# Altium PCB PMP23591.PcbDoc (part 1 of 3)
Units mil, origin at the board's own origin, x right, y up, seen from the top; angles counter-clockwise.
Board outline 3937.01 x 3937.01 mil, 6 copper layers (Top Layer, GND, Power Layer, Signal Layer, GND (Mid4), Bottom Layer), stack 66.824 mil thick; 197 components, 79 nets, 496 pads, 588 vias.
Unrouted connection lines stored in the file: 309.
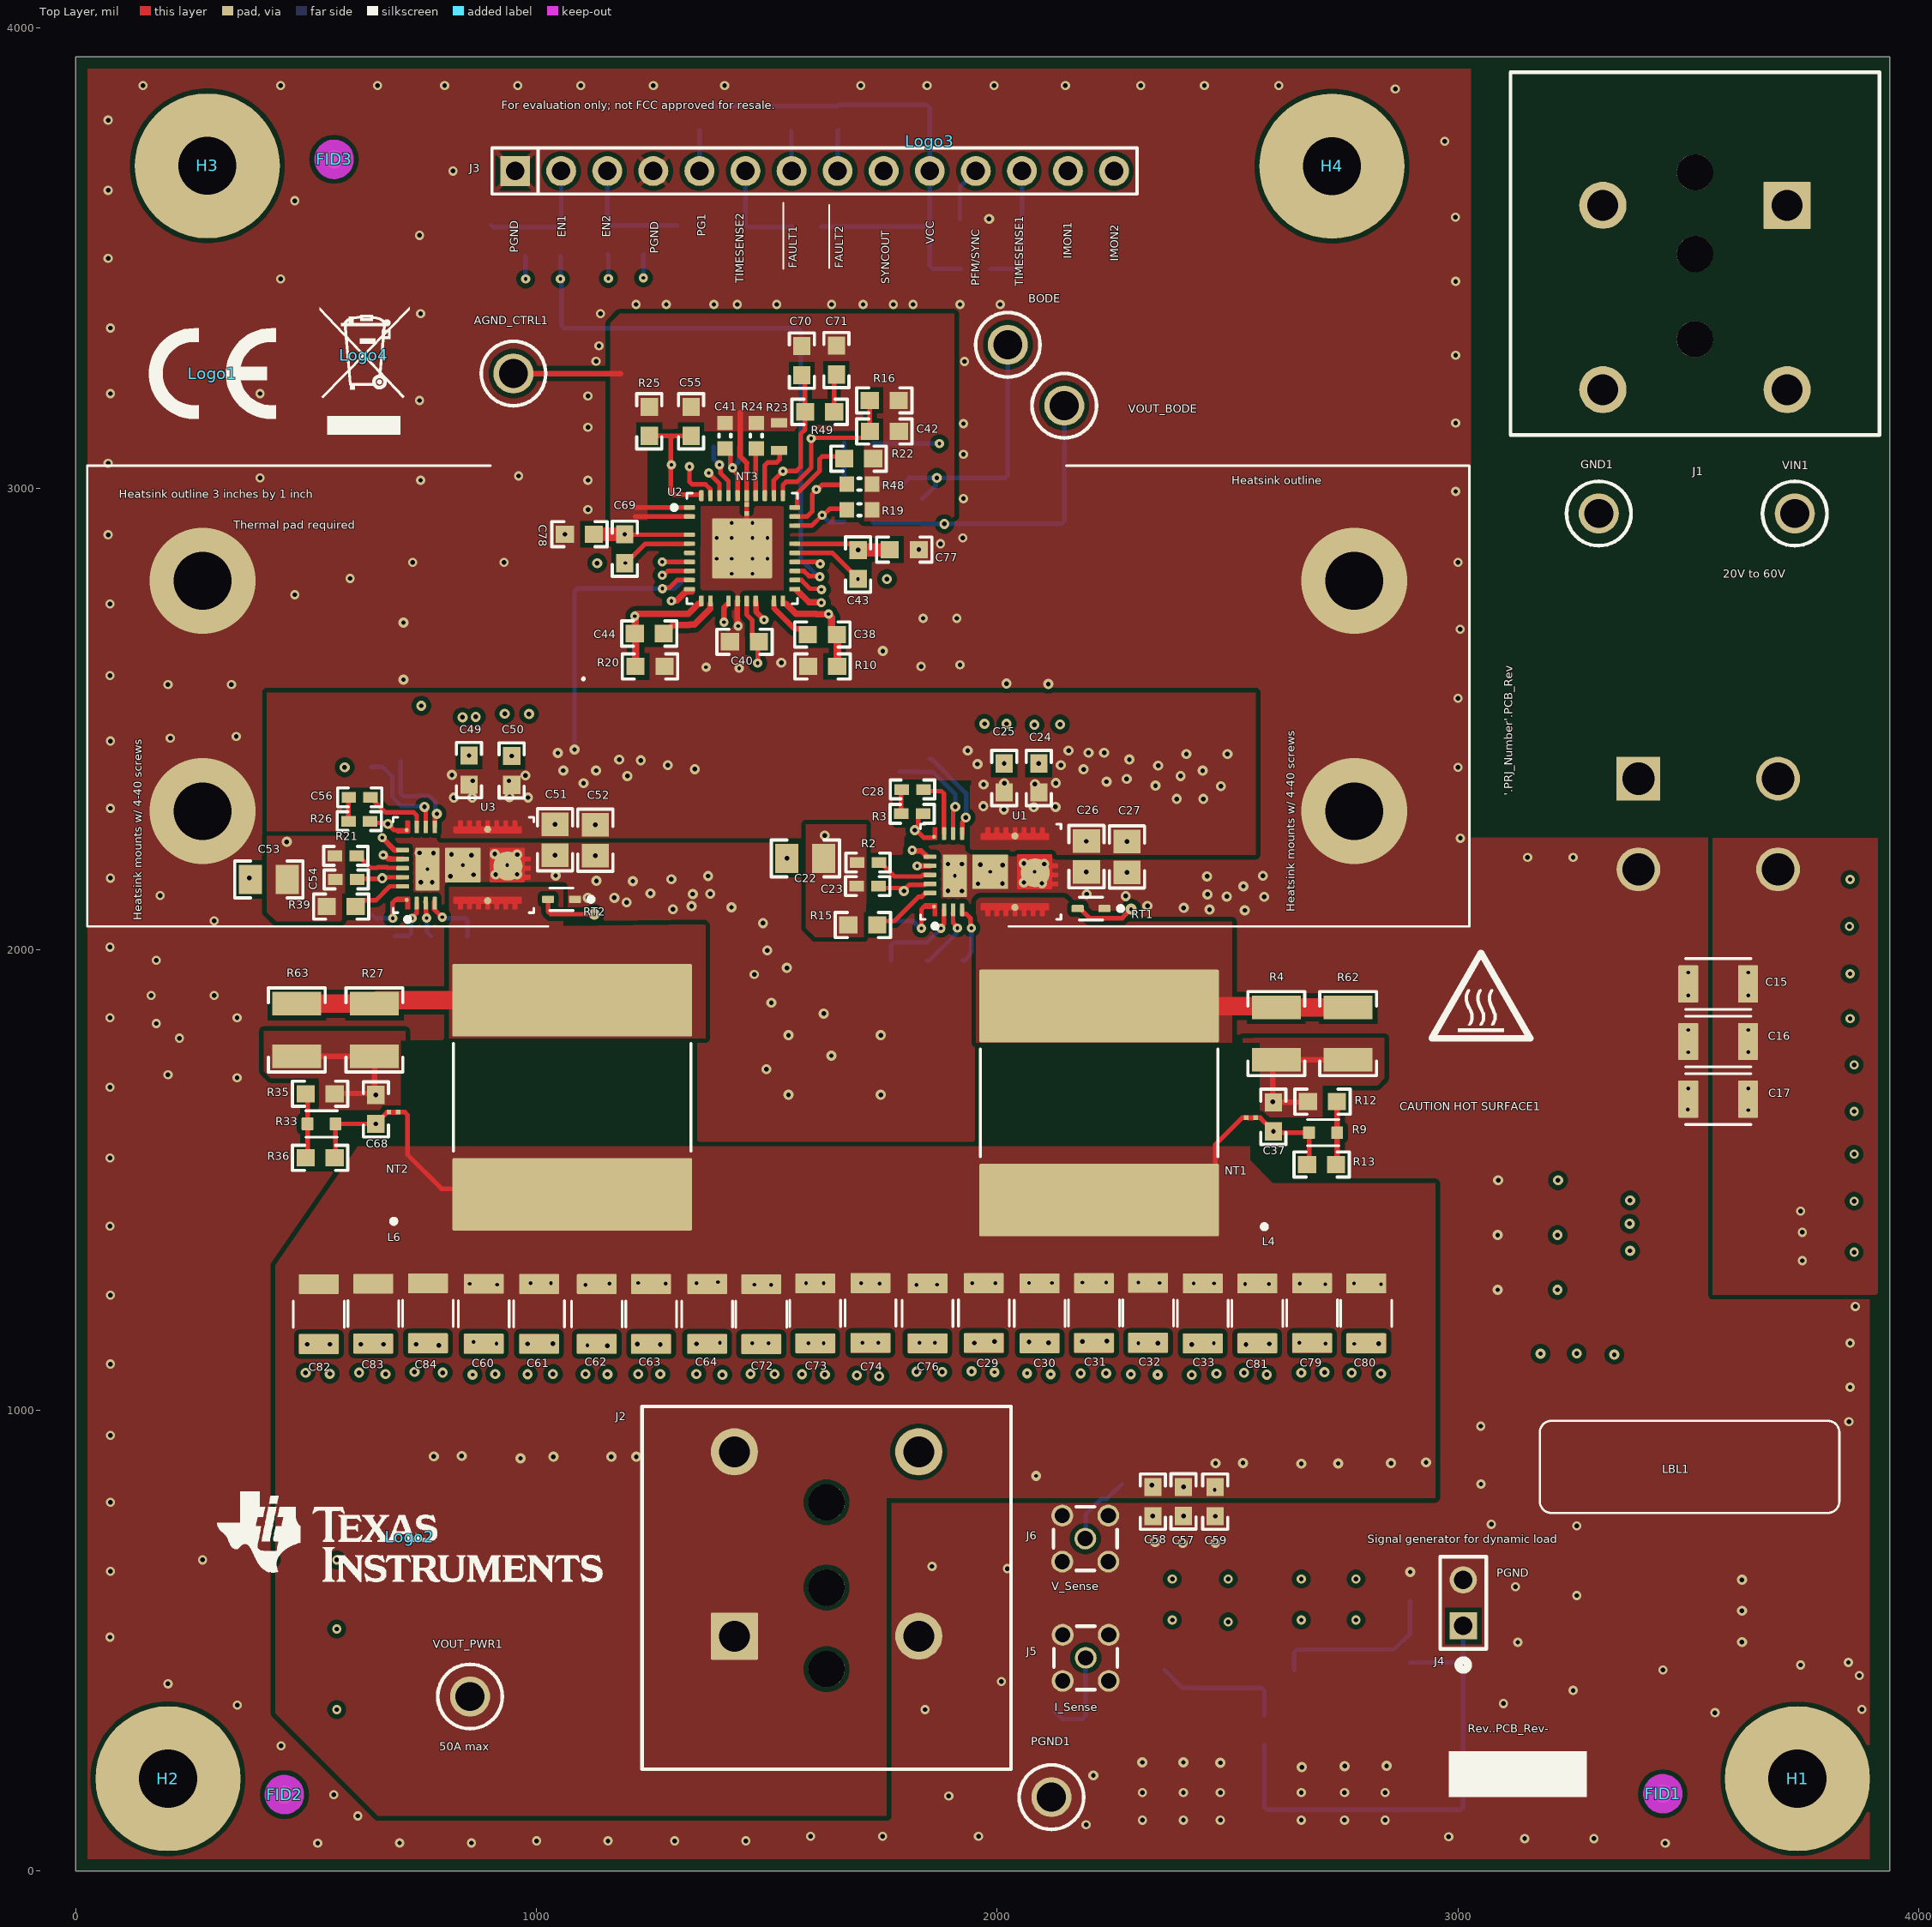
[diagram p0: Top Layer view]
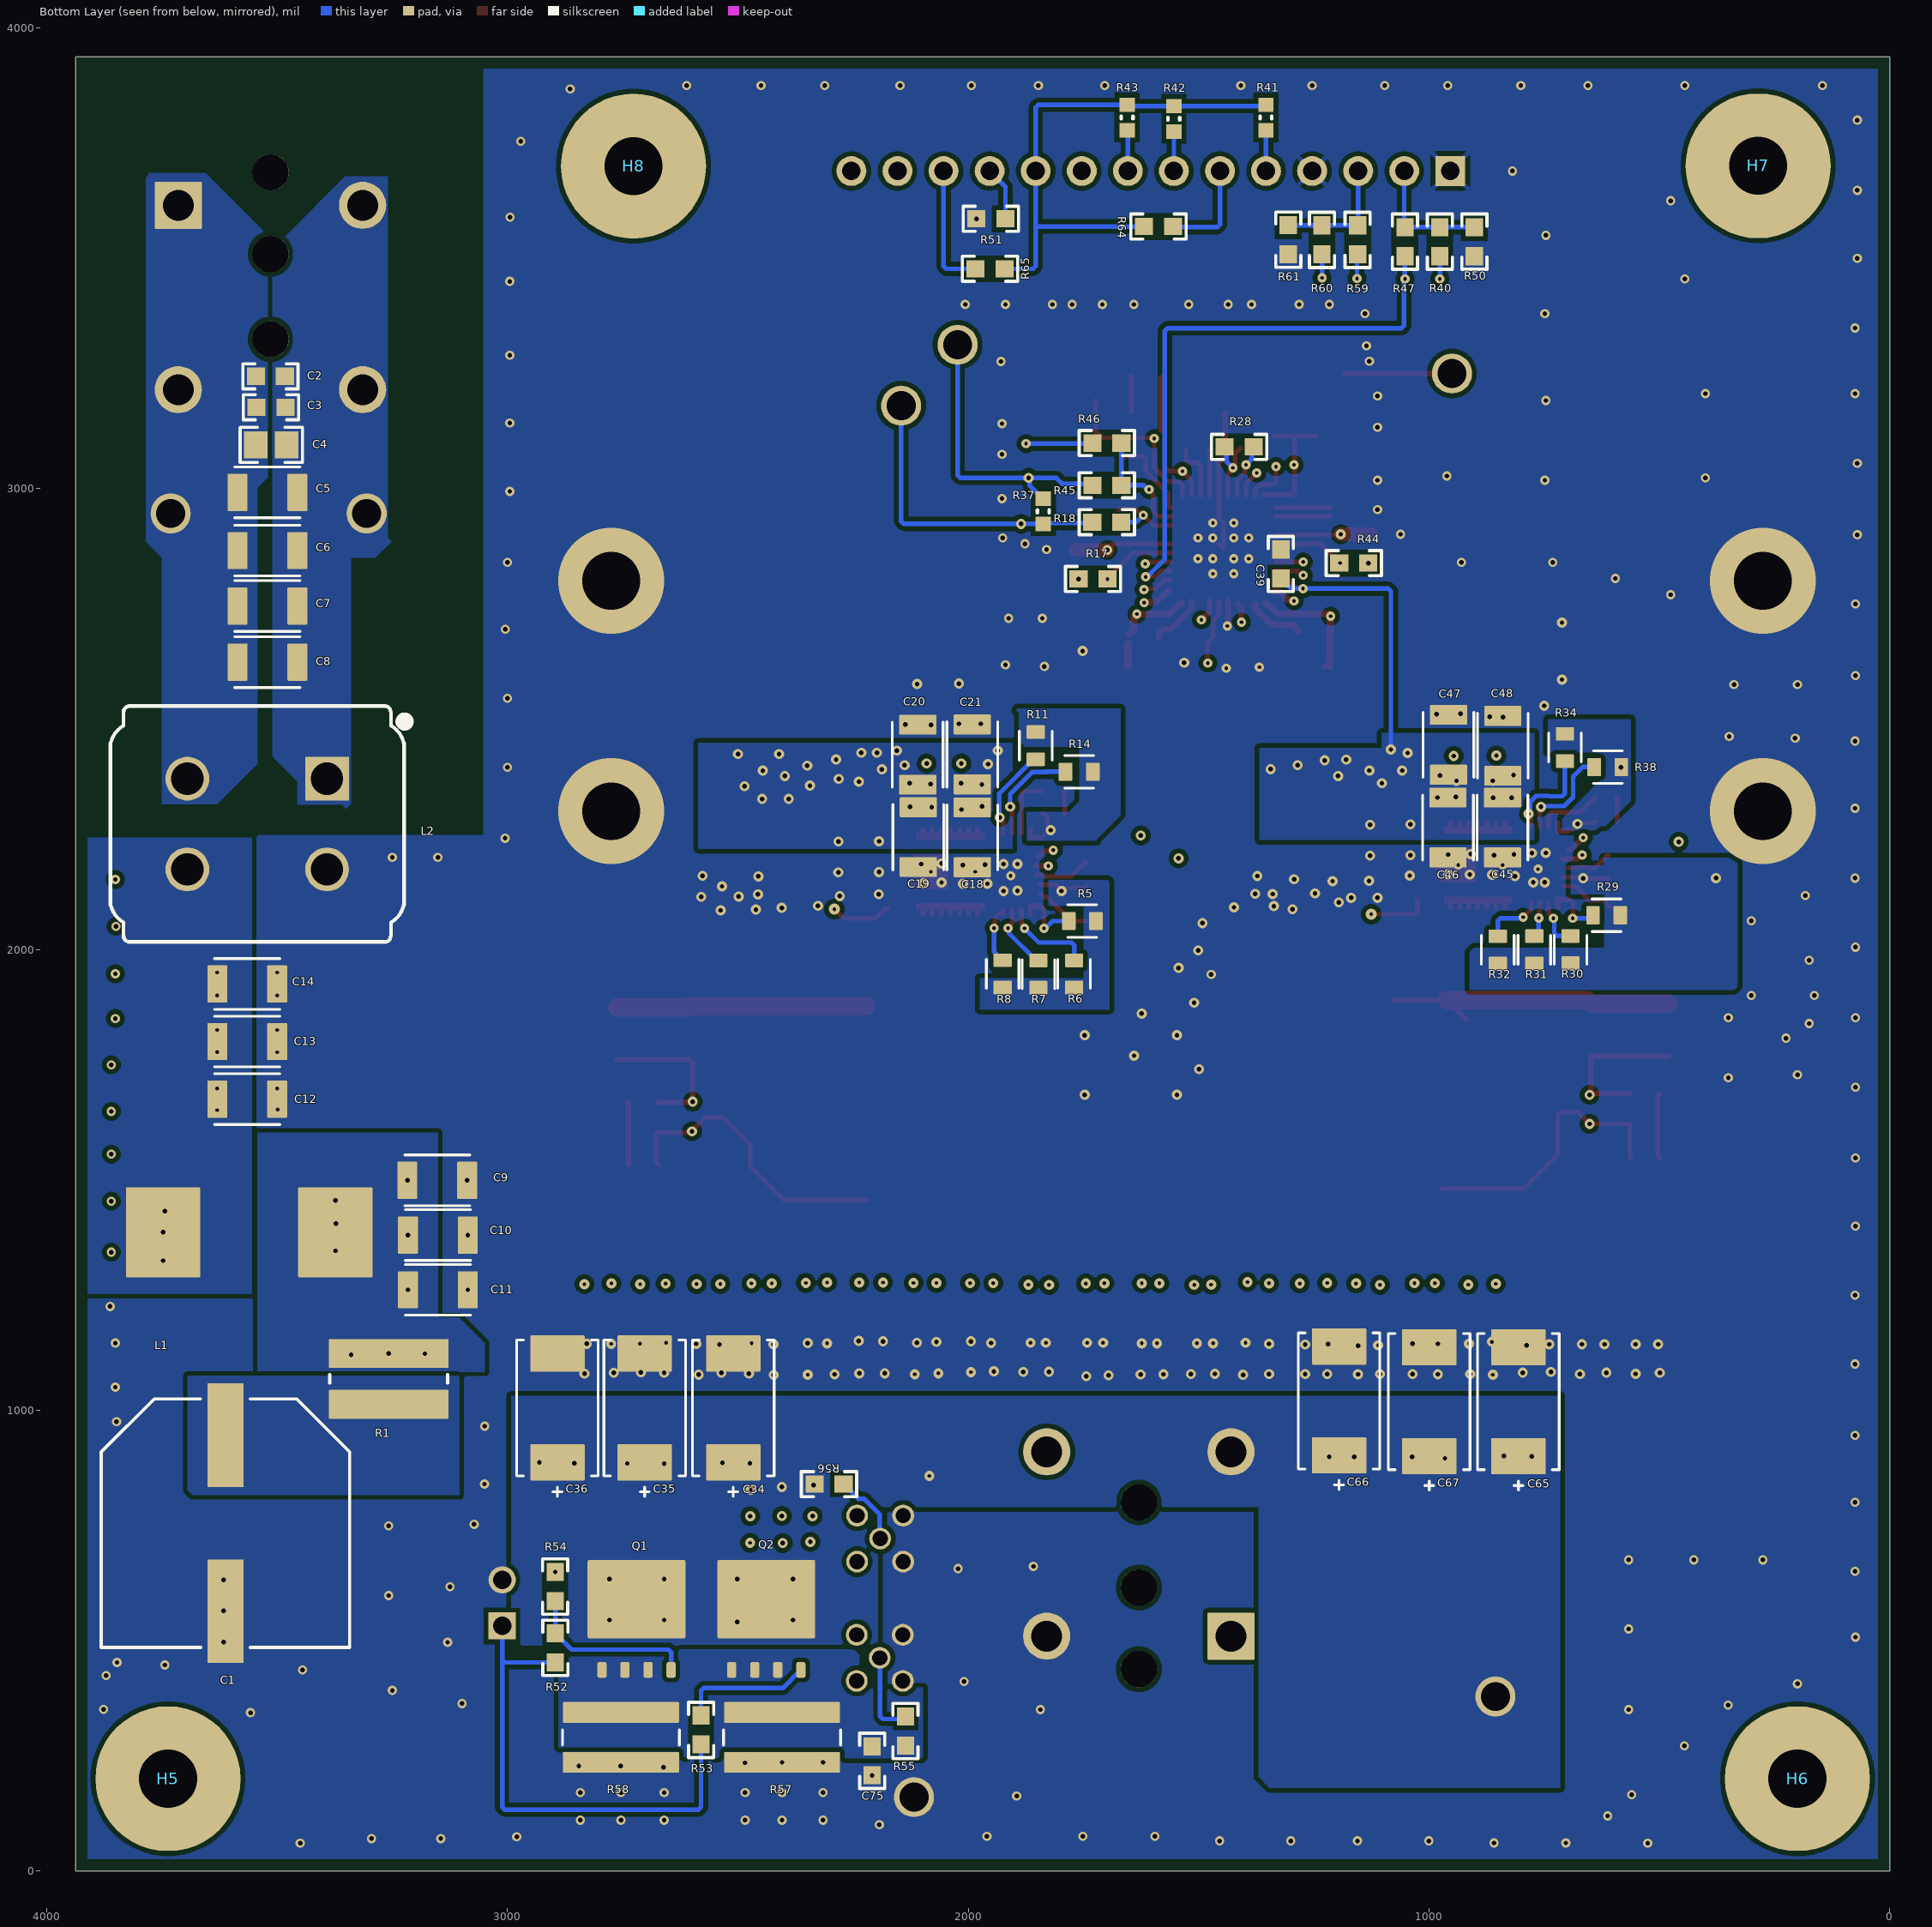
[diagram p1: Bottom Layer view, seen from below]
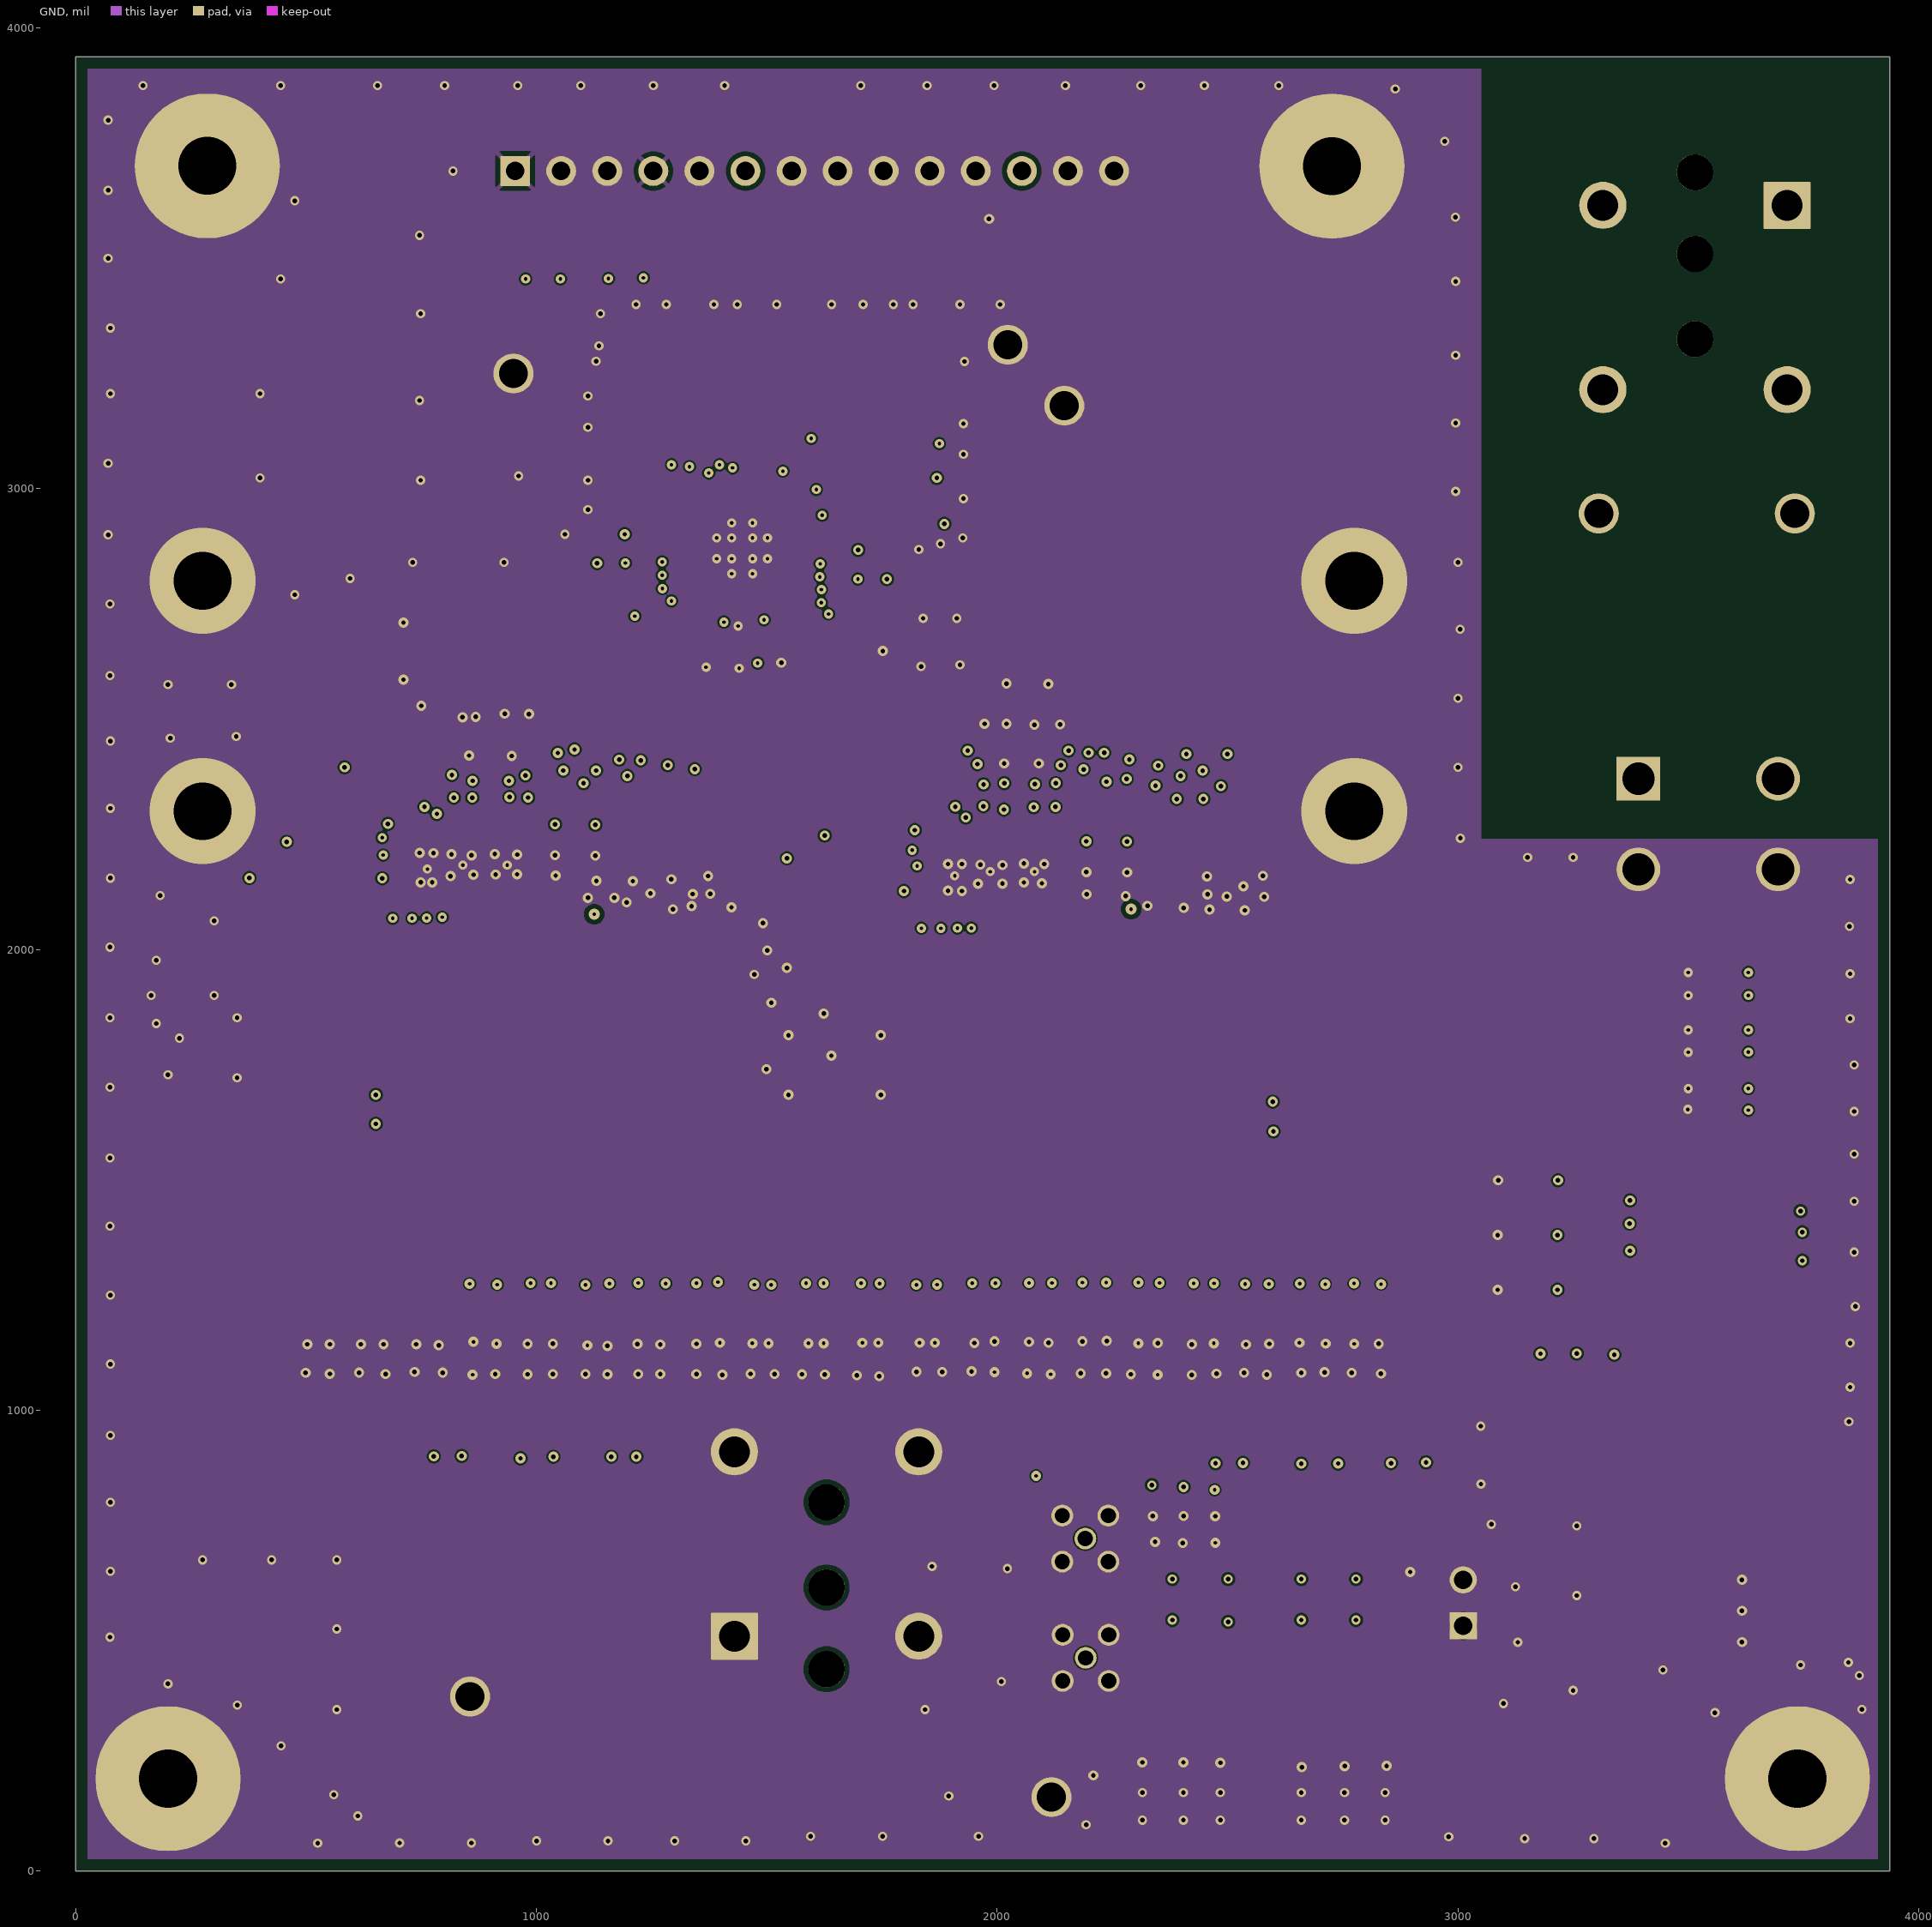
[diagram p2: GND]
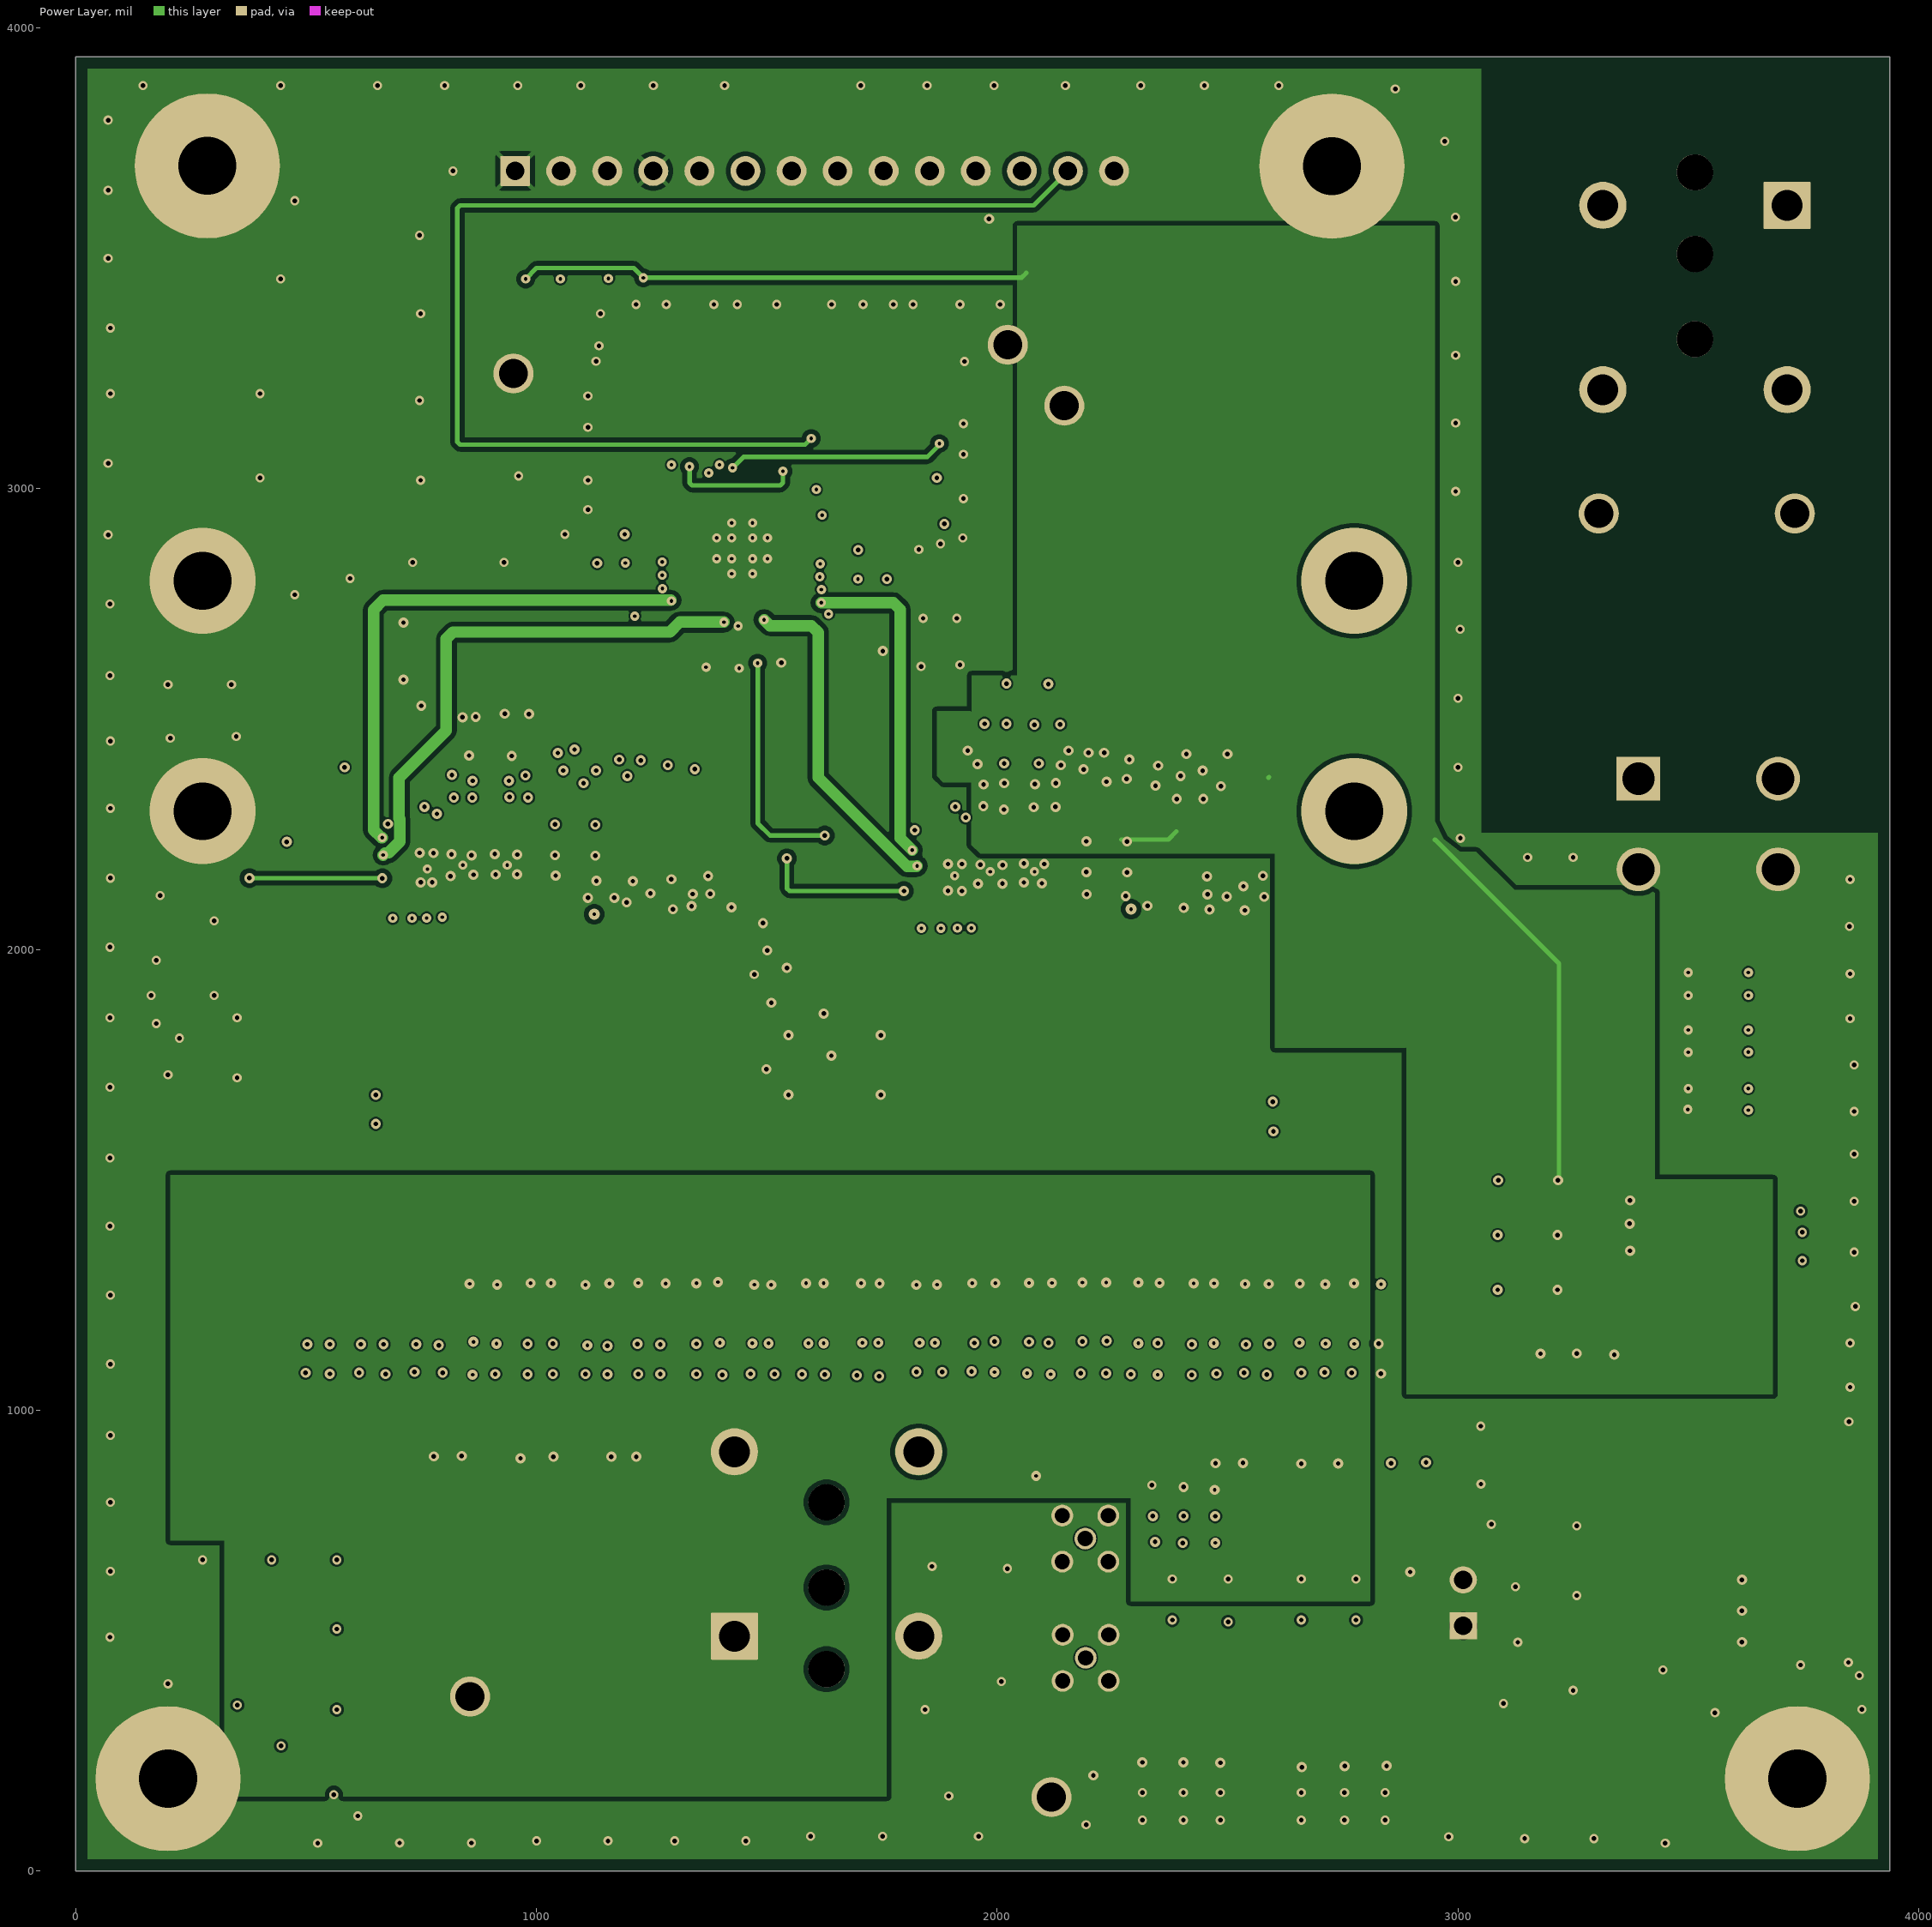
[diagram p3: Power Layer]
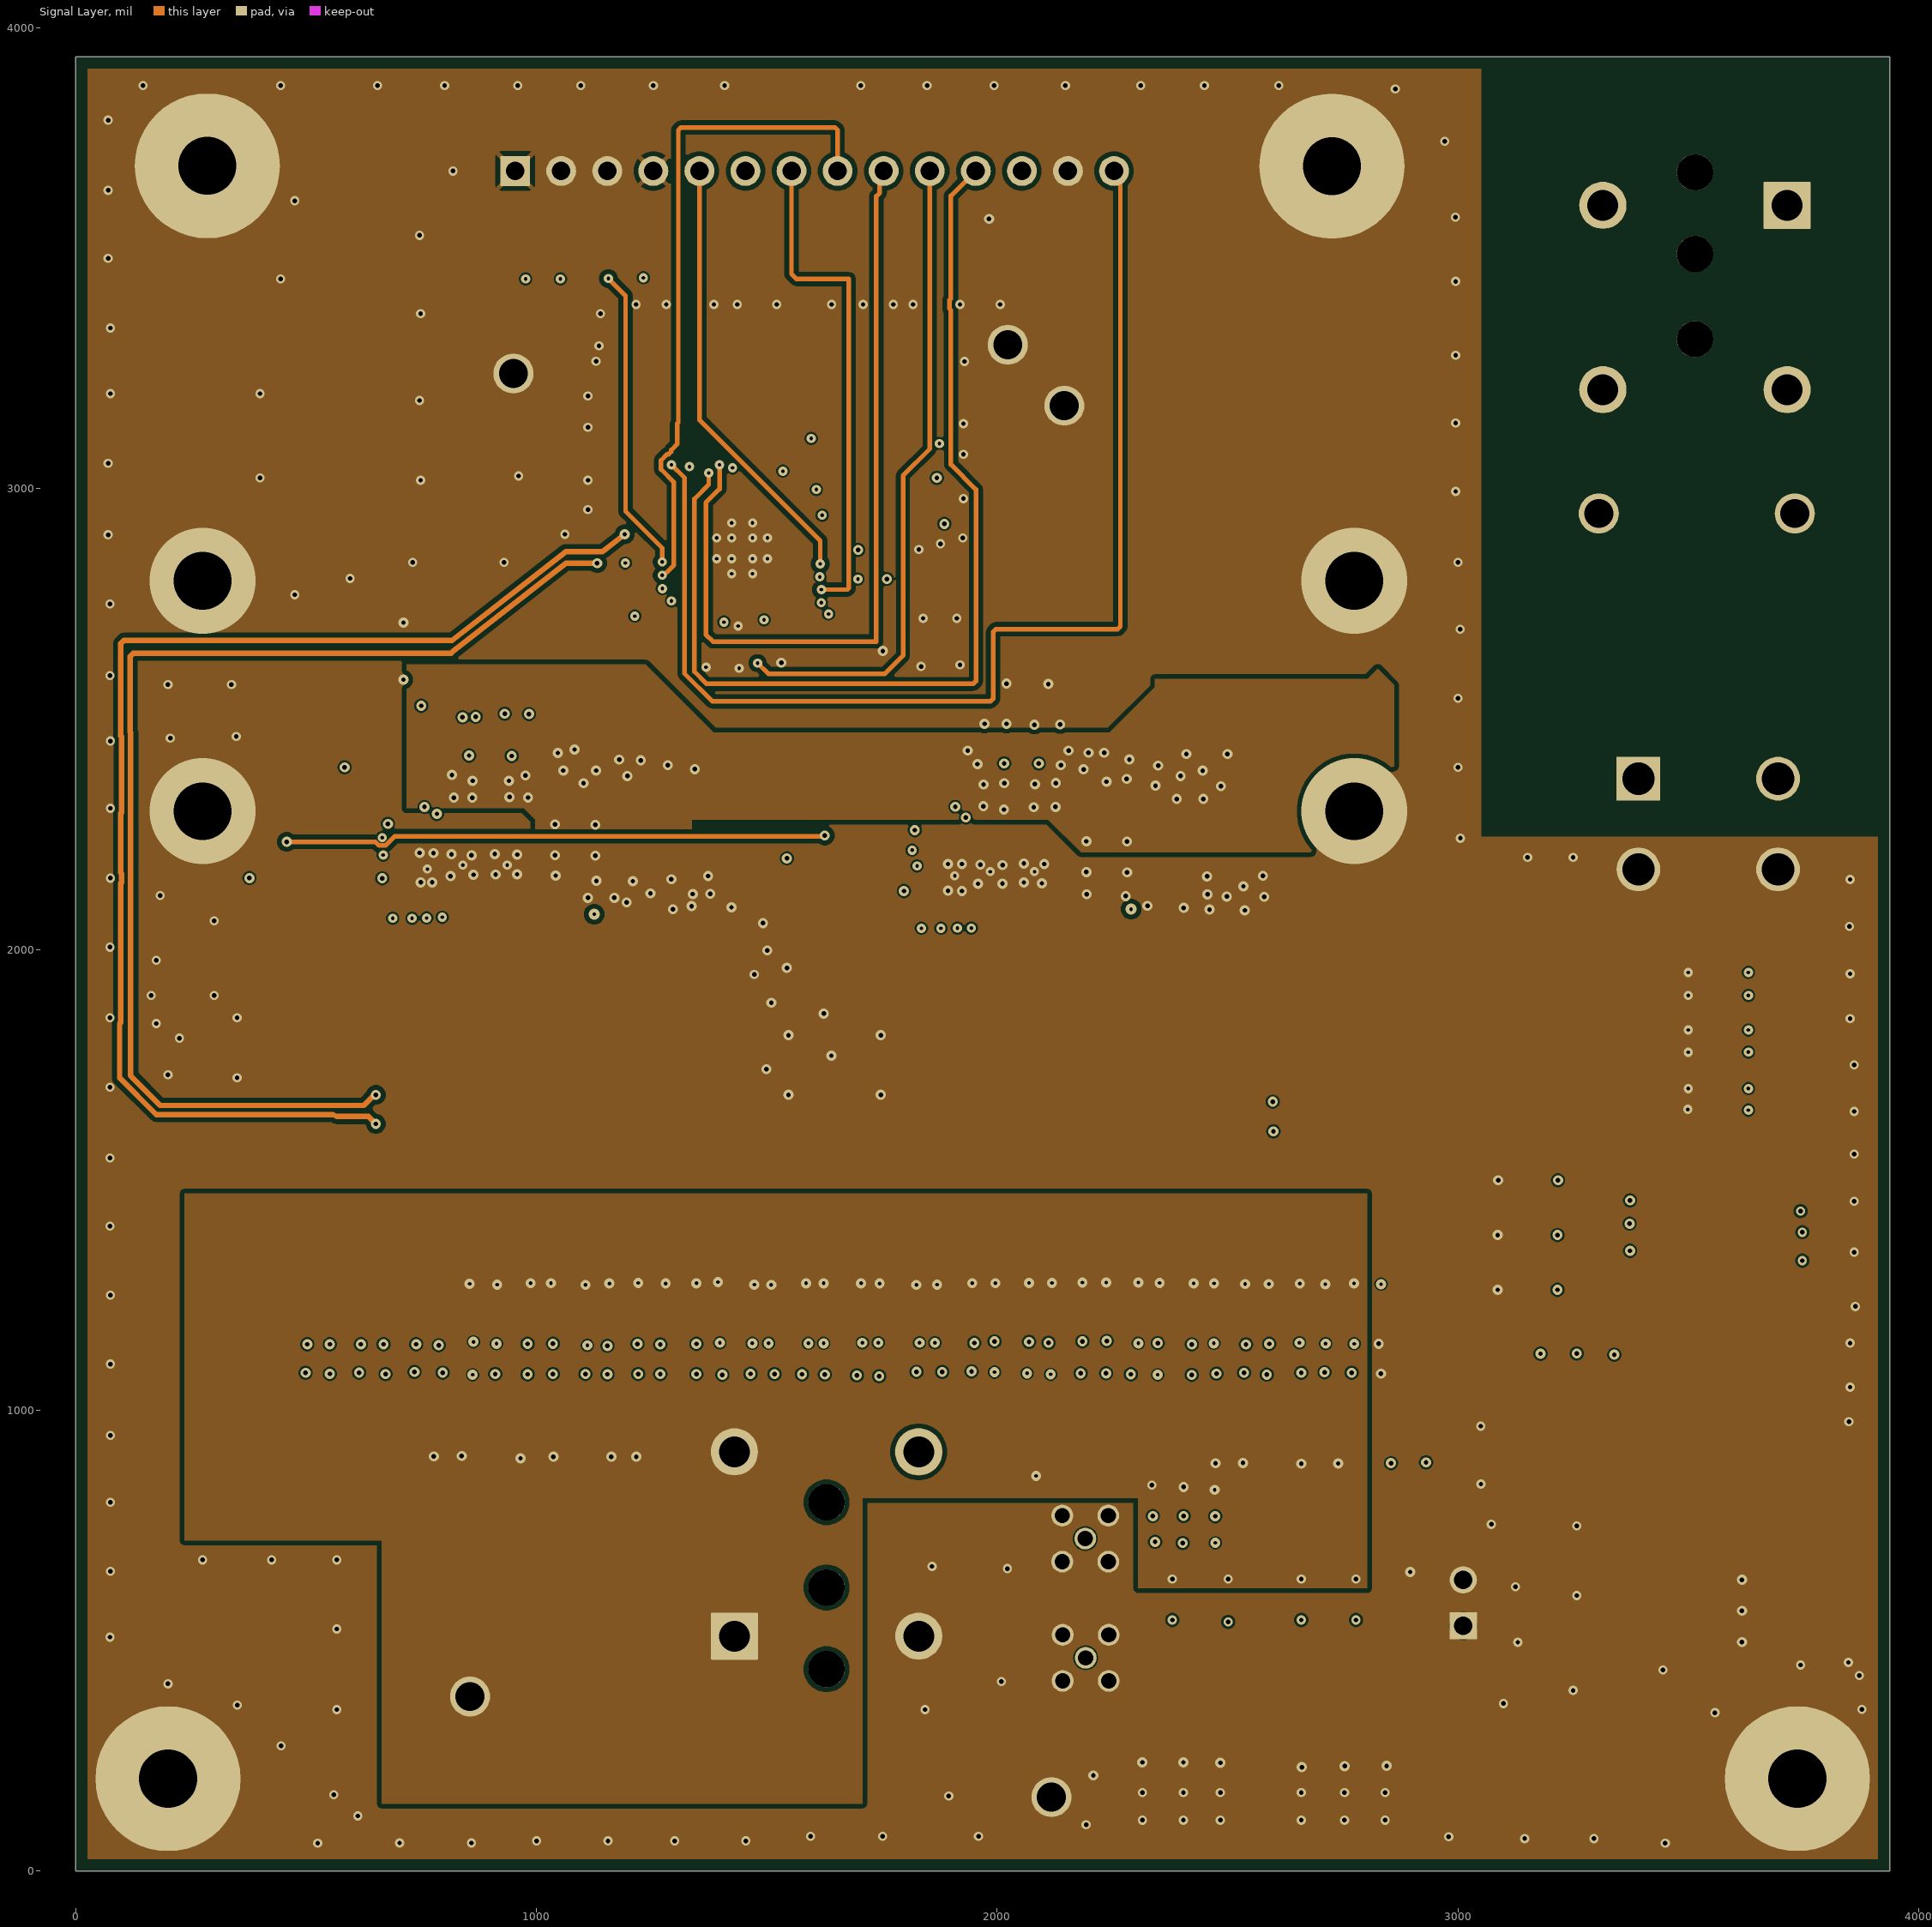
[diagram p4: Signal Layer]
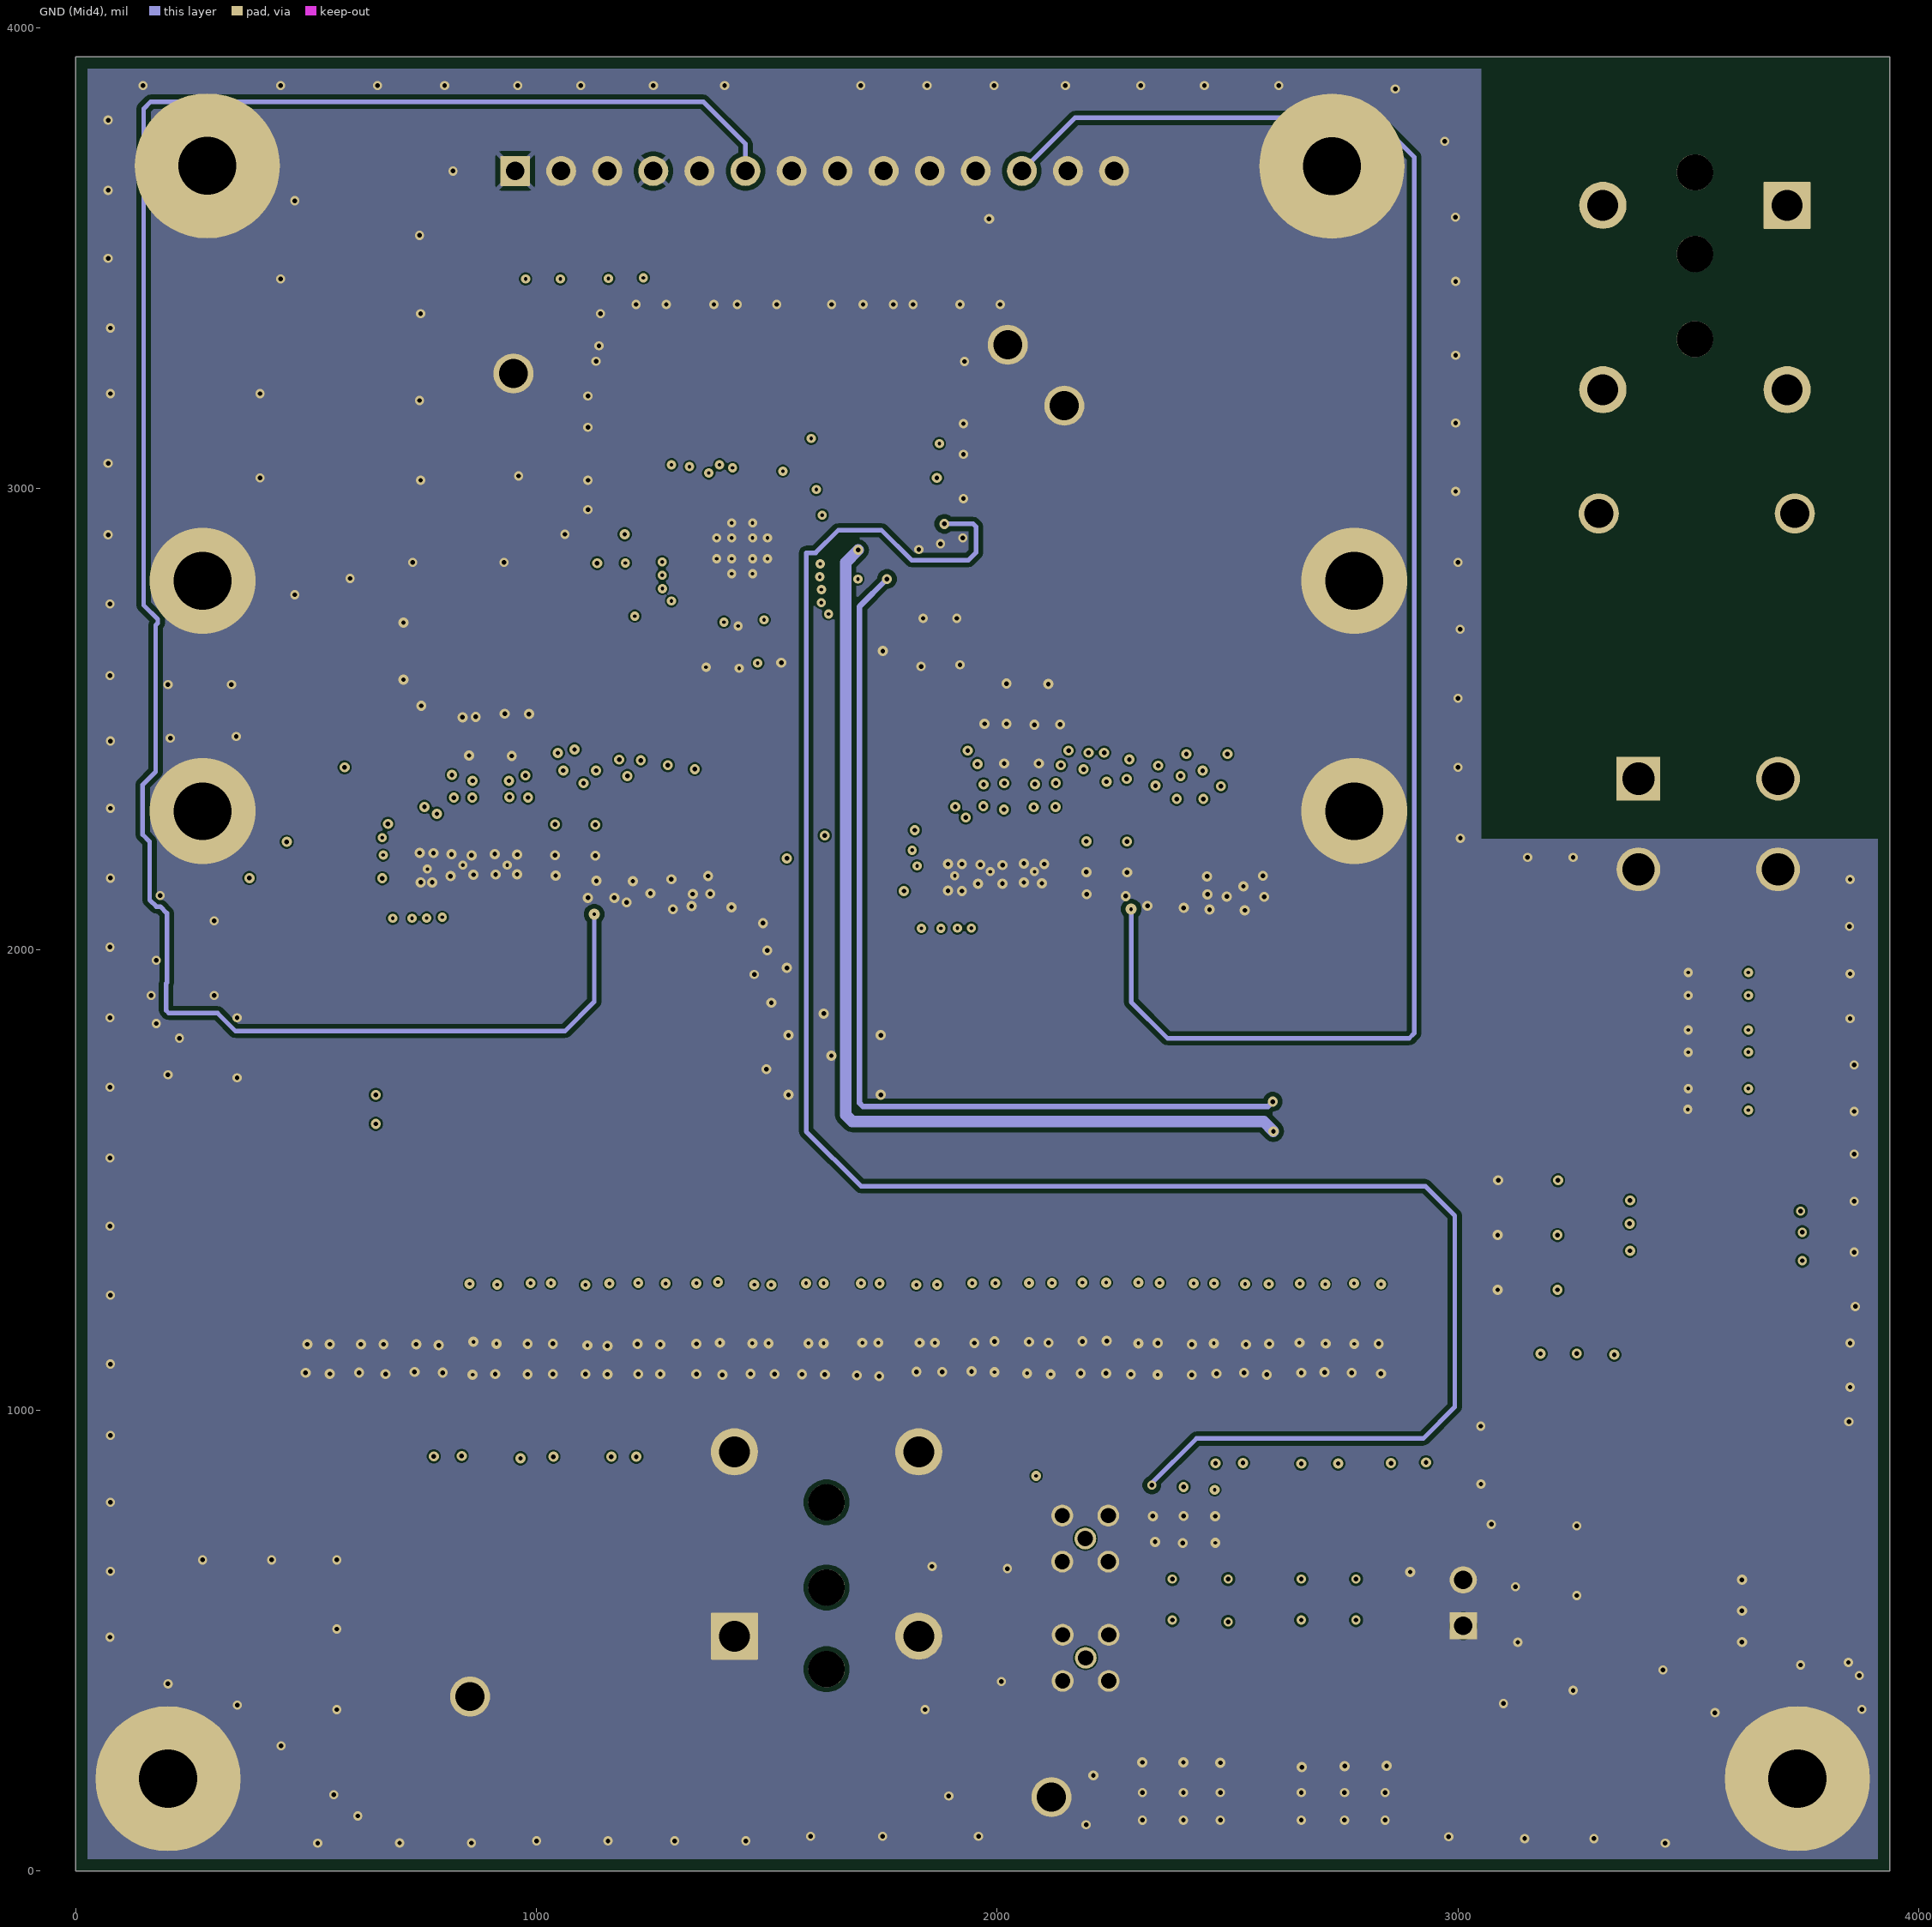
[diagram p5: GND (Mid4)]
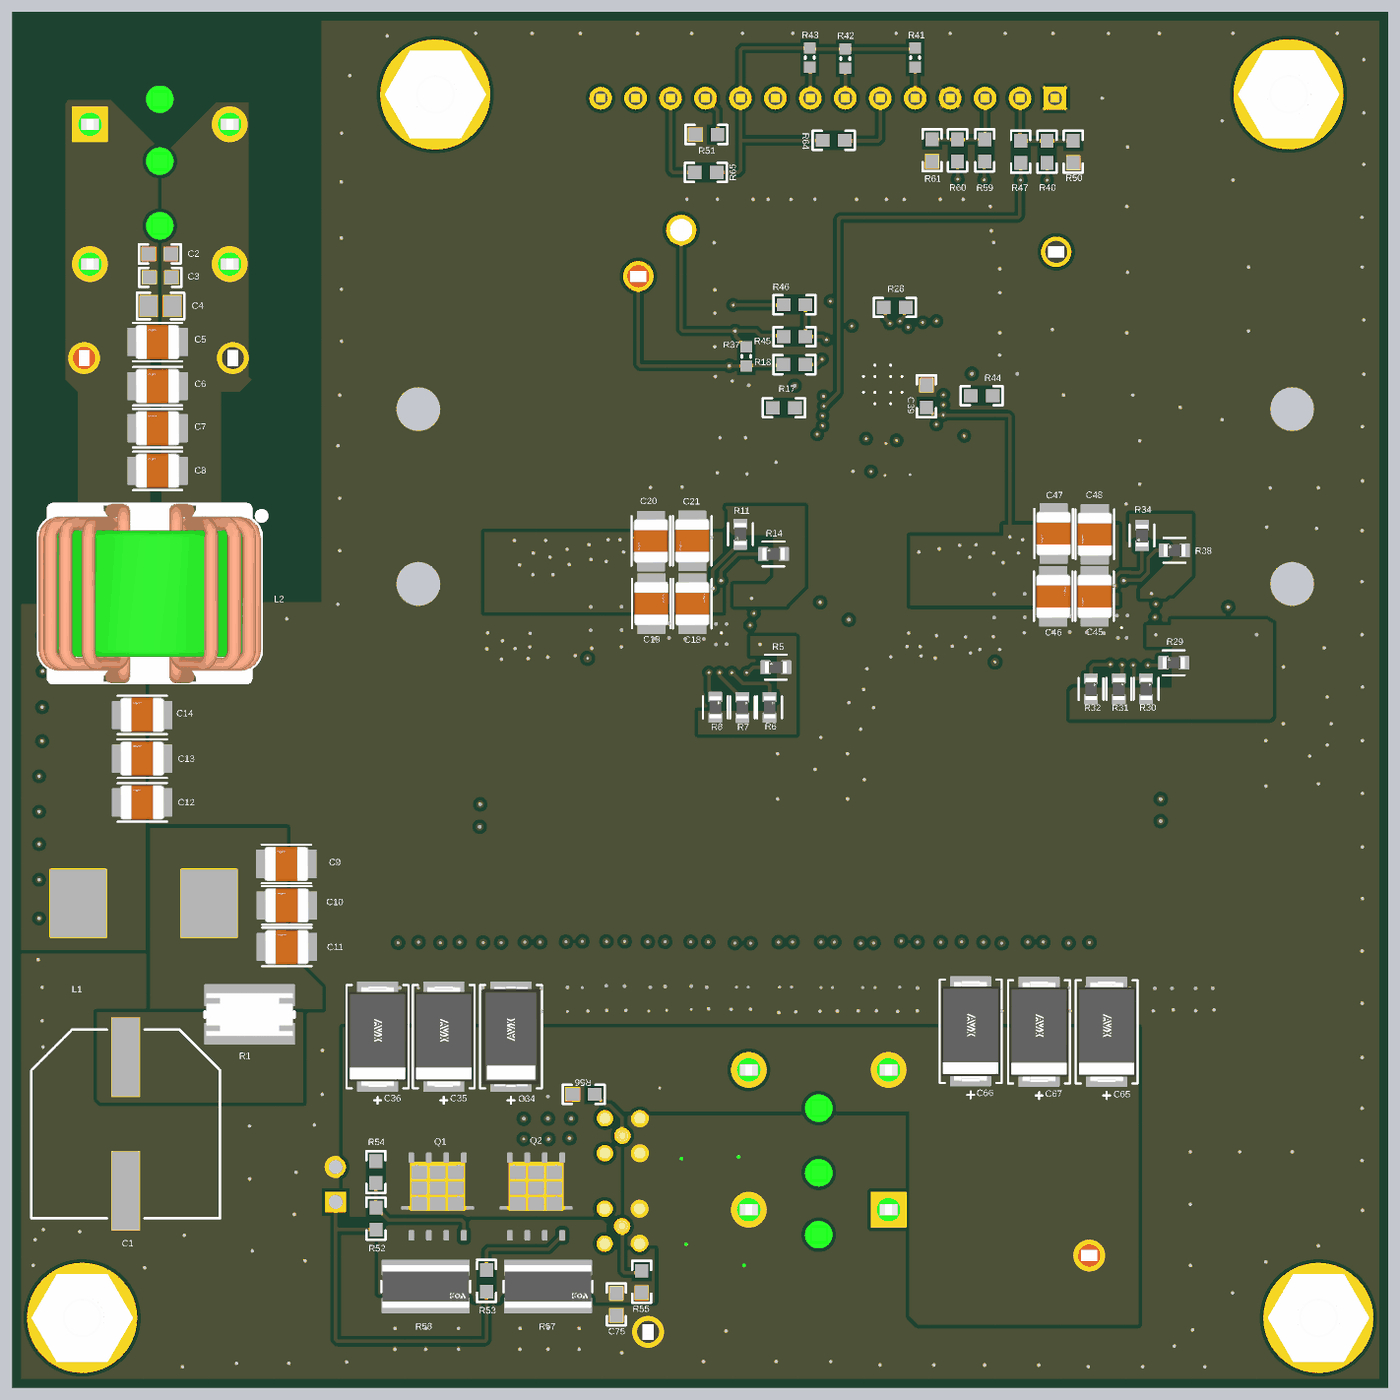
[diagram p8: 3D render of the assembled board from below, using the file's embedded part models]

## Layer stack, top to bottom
Top Solder: solder mask 0.5, Solder Resist, Dk 3.5
Top Layer: signal copper 2.8
Dielectric 1: prepreg 7, FR-4 High Tg, Dk 4.2
GND: signal copper 2.7559
Dielectric 2: core 14, FR-4 High Tg, Dk 4.2
Power Layer: signal copper 2.7559
Dielectric 4: prepreg 8.2, FR-4 High Tg, Dk 4.2
Signal Layer: signal copper 2.7559
Dielectric 5: core 14, FR-4 High Tg, Dk 4.2
GND (Mid4): signal copper 2.7559
Dielectric 3: prepreg 7, FR-4 High Tg, Dk 4.2
Bottom Layer: signal copper 2.8
Bottom Solder: solder mask 0.5, Solder Resist, Dk 3.5

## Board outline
0,0 3937.01,0 3937.01,3937.01 0,3937.01

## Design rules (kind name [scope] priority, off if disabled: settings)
AcuteAngle [All] p1: minimum=4.50000000000000E+0001 checktracksonly=TRUE
AssemblyTestPointUsage [All] p1: valid=2
BoardOutlineClearance BoardOutlineClearance_MountingHoles [OnCopper and InComponentClass('Mounting Holes')] p1: gap=40 ignorepadtopadclearanceinfootprint=FALSE
BoardOutlineClearance BoardOutlineClearance_Poly [OnCopper and IsPoly] p2: gap=25 ignorepadtopadclearanceinfootprint=FALSE
BoardOutlineClearance [OnCopper and Not InComponentClass('Logo') and not InComponentClass('FiducialMark') and not InRegion(1000,500,4000,800) and not InPoly] p3: gap=50 ignorepadtopadclearanceinfootprint=FALSE
Clearance "Clearance_EMI 2 Poly" [InNetClass('EMI-Clearance')] p1: gap=19.68 ignorepadtopadclearanceinfootprint=FALSE
Clearance Clearance_Keepouts [((IsTrack Or IsArc) And Not InPoly) And IsFree and IsKeepOut vs ((IsTrack Or IsArc) And Not InPoly) And IsFree and IsKeepOut] p2: gap=40 ignorepadtopadclearanceinfootprint=FALSE
Clearance Clearance_Poly [InPolygon] p3: gap=10 ignorepadtopadclearanceinfootprint=FALSE
Clearance Clearance_FiducialMark [IsKeepOut and InComponentClass('FiducialMark') vs IsPad and InComponentClass('FiducialMark')] p4: gap=0 ignorepadtopadclearanceinfootprint=FALSE
Clearance [All] p5: gap=7.87 ignorepadtopadclearanceinfootprint=FALSE except(0: Arc-Hole Track-Hole SMDPad-Hole THPad-Hole Via-Hole Fill-Hole Poly-Hole Region-Hole Text-Hole)
ComponentClearance ComponentClearanceGaN4_5 [InComponent('L5') vs InComponent('L6')] p1: gap=0 collisioncheckmode=3 verticalgap=0 showdistances=FALSE donotcheckwithout3dbody=TRUE
ComponentClearance ComponentClearanceGaN4 [InComponent('L3') vs InComponent('L4')] p2: gap=0 collisioncheckmode=3 verticalgap=0 showdistances=FALSE donotcheckwithout3dbody=TRUE
ComponentClearance "NET TIE" [HasFootprint('Net-Tie_10mil')] p3: gap=0 collisioncheckmode=3 verticalgap=0 showdistances=FALSE donotcheckwithout3dbody=TRUE
ComponentClearance ComponentClearance_NetTie [HasFootprint('Net-Tie_10mil')] p4: gap=0 collisioncheckmode=3 verticalgap=0 showdistances=FALSE
ComponentClearance "ComponentClearance_Sheild H2" [InComponentClass('VOUT2') vs InComponent('H2')] p5: gap=20 collisioncheckmode=3 verticalgap=5 showdistances=FALSE
ComponentClearance "ComponentClearance_Shield H1" [InComponentClass('VOUT1') vs InComponent('H1')] p6: gap=20 collisioncheckmode=3 verticalgap=5 showdistances=FALSE
ComponentClearance ComponentClearance_MountingHoles_FiducialMarks [InComponentClass('Mounting Holes') vs InComponentClass('FiducialMark')] p7: gap=50 collisioncheckmode=3 verticalgap=10 showdistances=FALSE
ComponentClearance ComponentClearance_Shunt [InComponentClass('Header') vs InComponentClass('Shunt')] p8: gap=0 collisioncheckmode=3 verticalgap=0 showdistances=FALSE
ComponentClearance ComponentClearance_Logo [InComponentClass('Logo')] p9: gap=50 collisioncheckmode=3 verticalgap=10 showdistances=FALSE
ComponentClearance ComponentClearance_ScrewToNut [(HasFootprint('NY PMS 440 0025 PH')) vs (HasFootprint('Keystone_1902C'))] p10: gap=5 collisioncheckmode=3 verticalgap=10 showdistances=FALSE
ComponentClearance ComponentClearance_MountingHoles [InComponentClass('Mounting Holes')] p11: gap=150 collisioncheckmode=3 verticalgap=100000 showdistances=FALSE
ComponentClearance ComponentClearance_SmallPassives [HasFootprint('0201*') or HasFootprint('0402*') or HasFootprint('0508') or HasFootprint('0603*') or HasFootprint('0612') or HasFootprint('0805*') or HasFootprint('0815*') or HasFootprint('0830*') or HasFootprint('1206*') or HasFootprint('1210*') or HasFootprint('1808*') or HasFootprint('1812*') or HasFootprint('1825*') or HasFootprint('2010*') or HasFootprint('2220*') or HasFootprint('2225*') or HasFootprint('2512*') or HasFootprint('2728*') or HasFootprint('3518*') vs HasFootprint('0201*') or HasFootprint('0402*') or HasFootprint('0508') or HasFootprint('0603*') or HasFootprint('0612') or HasFootprint('0805*') or HasFootprint('0815*') or HasFootprint('0830*') or HasFootprint('1206*') or HasFootprint('1210*') or HasFootprint('1808*') or HasFootprint('1812*') or HasFootprint('1825*') or HasFootprint('2010*') or HasFootprint('2220*') or HasFootprint('2225*') or HasFootprint('2512*') or HasFootprint('2728*') or HasFootprint('3518*')] p12: gap=12 collisioncheckmode=3 verticalgap=10 showdistances=FALSE
ComponentClearance ComponentClearance_Jumpers [HasFootprint('Harwin_M7582-05') vs HasFootprint('TSW-114-07-G-S')] p13: gap=0 collisioncheckmode=3 verticalgap=0 showdistances=FALSE
ComponentClearance ComponentClearance_THtoSMT [IsThruComponent vs IsSMTComponent] p14: gap=40 collisioncheckmode=3 verticalgap=30 showdistances=FALSE
ComponentClearance ComponentClearance_THtoTH [IsThruComponent vs IsThruComponent] p15: gap=30 collisioncheckmode=3 verticalgap=30 showdistances=FALSE
ComponentClearance Inductor [HasFootprint('FP-XGL6060-MFG') vs HasFootprint('FP-XGL1010-MFG')] p16: gap=0 collisioncheckmode=3 verticalgap=0 showdistances=FALSE
ComponentClearance ComponentClearance_L1 [HasFootprint('FP-XGL6060-332MEC_SMT_6MM51_6MM71-MFG') vs HasFootprint('VCHA105D')] p17: gap=0 collisioncheckmode=3 verticalgap=0 showdistances=FALSE
DiffPairsRouting [All] p1: maxlimit=100 minlimit=10 mostfreqgap=10 toplayer_minwidth=15 toplayer_maxwidth=15 toplayer_prefwidth=15 midlayer1_minwidth=15 midlayer1_maxwidth=15 midlayer1_prefwidth=15 midlayer2_minwidth=15 midlayer2_maxwidth=15 midlayer2_prefwidth=15 midlayer3_minwidth=15 midlayer3_maxwidth=15 midlayer3_prefwidth=15 midlayer4_minwidth=15 midlayer4_maxwidth=15 midlayer4_prefwidth=15 bottomlayer_minwidth=15 bottomlayer_maxwidth=15 bottomlayer_prefwidth=15 maxuncoupledlength=1000
FabricationTestPointUsage TestPointUsage [All] p1: valid=2 allowmultiple=FALSE
FabricationTestpoint Testpoint [All] p1: side=3 testpointundercomponent=TRUE minsize=40 maxsize=100 preferedsize=60 minholesize=0 maxholesize=40 preferedholesize=32 testpointgrid=1 allowsidetop=TRUE allowsidebottom=TRUE usegrid=TRUE gridtolerance=0.01
FanoutControl Fanout_LCC [IsLCC] p1: bgadir=Out bgaviamode=Centered fanoutstyle=Auto fanoutdirection=Alternating viagrid=1 // Fanout_LCC (Default Rule)
FanoutControl Fanout_BGA [IsBGA] p2: bgadir=Out bgaviamode=Centered fanoutstyle=Auto fanoutdirection=Alternating viagrid=1 // Fanout_BGA (Default Rule)
FanoutControl Fanout_Default [All] p4: bgadir=Out bgaviamode=Centered fanoutstyle=Auto fanoutdirection=Alternating viagrid=1 // Fanout_Default (Default Rule)
FanoutControl Fanout_Small [(CompPinCount < 5)] p5: bgadir=Out bgaviamode=Centered fanoutstyle=Auto fanoutdirection=OutThenIn viagrid=1 // Fanout_Small (Default Rule)
HoleSize [All] p1: absolutevalues=TRUE maxlimit=275 minlimit=7.87 maxpercent=80.000 minpercent=20.000
MinimumAnnularRing MinimumAnnularRing_ThermalPadVias [IsVia and InAnyComponent] p1: minimumring=5.91
MinimumAnnularRing [All] p2: minimumring=5
MinimumSolderMaskSliver MinimumSolderMaskSliver_Logo [InComponentClass('Logo') vs InComponentClass('Logo')] p1: minsoldermaskwidth=0.7
MinimumSolderMaskSliver [All] p2: minsoldermaskwidth=3.94
PlaneClearance [All] p1: clearance=10
PolygonConnect "PolygonConnect_J4 PGND" [HasFootprint('TSW-114-07-G-S') vs InNet('PGND')] p1: connectstyle=Relief reliefconductorwidth=10 reliefentries=4 polygonreliefangle="45 Angle" airgapwidth=10
PolygonConnect [All] p2: connectstyle=Direct reliefconductorwidth=10 reliefentries=4 polygonreliefangle="45 Angle" airgapwidth=10
RoutingVias ThermalPadVias [IsVia and InAnyComponent] p1: holewidth=7.87 width=19.68 viastyle="Through Hole" minholewidth=7.87 minwidth=19.68 maxholewidth=16 maxwidth=32
RoutingVias [All] p2: holewidth=10 width=22 viastyle="Through Hole" minholewidth=7.87 minwidth=20 maxholewidth=200 maxwidth=265
SilkToBoardRegionClearance [Not ((IsComment or IsDesignator) And (Hide <> 'False')) and not InRegion(1000,500,4000,800)] p1:
SilkToSilkClearance SilkToSilkClearance_Pb-FreeLogo [(HasFootprint('Pb-Free_Overlay_Medium') OR HasFootprint('Pb-Free_Overlay_Small')) vs (HasFootprint('Pb-Free_Overlay_Medium') OR HasFootprint('Pb-Free_Overlay_Small'))] p1: silktosilkclearance=0
SilkToSilkClearance [All] p2: silktosilkclearance=4
SilkToSolderMaskClearance [IsPad] p1: minsilkscreentomaskgap=3.9 clearancetoexposedcopper=TRUE
SilkToSolderMaskClearance SilkToComponentPadClearance [(IsPad or IsFill or IsRegion) and InAnycomponent] p2: minsilkscreentomaskgap=3.9 clearancetoexposedcopper=TRUE
SolderMaskExpansion [All] p1: expansion=1.97 istentingtop=FALSE
SupplyNets "Schematic Supply Nets_10" [InNet('VCC')] p1: voltage=0.000
SupplyNets "Schematic Supply Nets_9" [InNet('PGND')] p2: voltage=0.000
SupplyNets "Schematic Supply Nets_8" [InNet('HS1')] p3: voltage=0.000
SupplyNets "Schematic Supply Nets_7" [InNet('VIN')] p4: voltage=0.000
SupplyNets "Schematic Supply Nets_6" [InNet('AGND2')] p5: voltage=0.000
SupplyNets "Schematic Supply Nets_5" [InNet('AGND')] p6: voltage=0.000
SupplyNets "Schematic Supply Nets_4" [InNet('HS2')] p7: voltage=0.000
SupplyNets "Schematic Supply Nets_3" [InNet('AGND3')] p8: voltage=0.000
SupplyNets "Schematic Supply Nets_2" [InNet('Vout')] p9: voltage=0.000
SupplyNets "Schematic Supply Nets_1" [InNet('VDDA')] p10: voltage=0.000
SupplyNets "Schematic Supply Nets" [InNet('FB')] p11: voltage=0.000
Width [All] p1: maxlimit=100 minlimit=6 preferedwidth=10 checkconnectedcopper=TRUE
15 further rules are at their usual default settings.

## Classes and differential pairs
component class PMP23591.DynamicLoad: C57 C58 C59 C75 J4 J5 J6 Q1 Q2 R52 R53 R54 R55 R56 R57 R58
net class LV: NetC75_2 NetJ4_1 NetJ5_1 NetJ6_1 NetQ1_4
net class HV: +Vin_Main VIN
component class Header: J3 J4
component class "Mounting Holes": H1 H2 H3 H4
component class Logo: Logo2
component class PMP23591_Hardware: "CAUTION HOT SURFACE1" FID1 FID2 FID3 H1 H2 H3 H4 H5 H6 H7 H8 LBL1 Logo1 Logo2 Logo3 Logo4 ZZ1 ZZ2 ZZ3 ZZ4
component class FiducialMark: FID1 FID2 FID3
component class AssemblyNote: ZZ1 ZZ2 ZZ3 ZZ4
component class Label: LBL1

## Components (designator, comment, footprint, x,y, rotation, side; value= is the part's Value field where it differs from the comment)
AGND_CTRL1 "AGND_CTRL" Keystone5011 949.94,3250 r90 top
BODE "BODE" Keystone5012 2023.01,3312.4 r90 top
C1 "EEV-FK1K101Q" SM_RADIAL_H13 3612.2,754.71 r270 bottom value=100uF
C2 "CGA3E2X7R2A102K080AA" 0603 3514.65,3243.98 r180 bottom value=1000pF
C3 "GRM188R72A103KA01D" 0603 3513.47,3176.93 r0 bottom value=0.01uF
C4 "C0805C104K1RACTU" 0805 3512.68,3095 r180 bottom value=0.1uF
C5 "GCJ32DC72A475KE01L" FP-GCJ32DC72A475KE01L_1210-MFG 3521.15,2991.94 r0 bottom value=4.7µF
C6 "GCJ32DC72A475KE01L" FP-GCJ32DC72A475KE01L_1210-MFG 3521.15,2865.79 r0 bottom value=4.7µF
C7 "GCJ32DC72A475KE01L" FP-GCJ32DC72A475KE01L_1210-MFG 3521.15,2745.4 r0 bottom value=4.7µF
C8 "GCJ32DC72A475KE01L" FP-GCJ32DC72A475KE01L_1210-MFG 3521.15,2623.53 r0 bottom value=4.7µF
C9 "GCJ32DC72A475KE01L" FP-GCJ32DC72A475KE01L_1210-MFG 3152.43,1498.79 r0 bottom value=4.7µF
C10 "GCJ32DC72A475KE01L" FP-GCJ32DC72A475KE01L_1210-MFG 3151.25,1380 r0 bottom value=4.7µF
C11 "GCJ32DC72A475KE01L" FP-GCJ32DC72A475KE01L_1210-MFG 3151.25,1261.25 r0 bottom value=4.7µF
C12 "GCJ32DC72A475KE01L" FP-GCJ32DC72A475KE01L_1210-MFG 3565,1675 r0 bottom value=4.7µF
C13 "GCJ32DC72A475KE01L" FP-GCJ32DC72A475KE01L_1210-MFG 3565,1800 r0 bottom value=4.7µF
C14 "GCJ32DC72A475KE01L" FP-GCJ32DC72A475KE01L_1210-MFG 3565,1925 r0 bottom value=4.7µF
C15 "GCJ32DC72A475KE01L" FP-GCJ32DC72A475KE01L_1210-MFG 3565,1925 r0 top value=4.7µF
C16 "GCJ32DC72A475KE01L" FP-GCJ32DC72A475KE01L_1210-MFG 3565,1800 r0 top value=4.7µF
C17 "GCJ32DC72A475KE01L" FP-GCJ32DC72A475KE01L_1210-MFG 3565,1675 r0 top value=4.7µF
C18 "GCJ32DC72A475KE01L" FP-GCJ32DC72A475KE01L_1210-MFG 1991.12,2243.17 r90 bottom value=4.7µF
C19 "GCJ32DC72A475KE01L" FP-GCJ32DC72A475KE01L_1210-MFG 2108.37,2243.63 r90 bottom value=4.7µF
C20 "GCJ32DC72A475KE01L" FP-GCJ32DC72A475KE01L_1210-MFG 2109.56,2422.67 r270 bottom value=4.7µF
C21 "GCJ32DC72A475KE01L" FP-GCJ32DC72A475KE01L_1210-MFG 1991.21,2423.11 r270 bottom value=4.7µF
C22 "GCM21BC71E475KE36L" 0805_HV 1583.46,2197.61 r180 top value=4.7uF
C23 "GCM155R71C104JA55D" 0402 1718.86,2137.45 r0 top value=0.1uF
C24 "CGA3E2X7R1E104K080AA" 0603 2090.28,2372.07 r270 top value=0.1uF
C25 "CGA3E2X7R1E104K080AA" 0603 2015.01,2372.07 r270 top value=0.1uF
C26 "CL21B224KCFSNWE" 0805 2193.58,2201.3 r270 top value=0.22uF
C27 "CL21B224KCFSNWE" 0805 2281.63,2200.68 r270 top value=0.22uF
C28 "GCM155R71C104JA55D" 0402 1816.07,2347.1 r0 top value=0.1uF
C29 "CGA6P3X7R1E226M250AB" FP-CGA6P3X7R1E226M250AB_1210-MFG 1971.06,1210.77 r90 top value=22µF
C30 "CGA6P3X7R1E226M250AB" FP-CGA6P3X7R1E226M250AB_1210-MFG 2092.17,1210.12 r90 top value=22µF
C31 "CGA6P3X7R1E226M250AB" FP-CGA6P3X7R1E226M250AB_1210-MFG 2210.05,1210.77 r90 top value=22µF
C32 "CGA6P3X7R1E226M250AB" FP-CGA6P3X7R1E226M250AB_1210-MFG 2327.53,1211.14 r90 top value=22µF
C33 "CGA6P3X7R1E226M250AB" FP-CGA6P3X7R1E226M250AB_1210-MFG 2446.09,1209.98 r90 top value=22µF
C34 "TCME227M016R0025E" FP-TCME227M016R0025E_2917-MFG 2509.99,1004.69 r270 bottom value=220µF
C35 "TCQE157M016R0025E" FP-TCQE157M016R0025E_2917-MFG 2702.35,1004.69 r270 bottom value=150µF
C36 "TCQE157M016R0025E" FP-TCQE157M016R0025E_2917-MFG 2891.7,1004.69 r270 bottom value=150µF
C37 "UMK107AB7105KA-T" 0603 2599.45,1636.68 r90 top value=1uF
C38 "CGA3E2X7R1E104K080AA" 0603 1620.54,2683.36 r180 top value=0.1uF
C39 "GRM188R72A104KA35D" 0603 1321.22,2836.59 r90 bottom value=0.1uF
C40 "GRM188Z71C475KE21D" 0603 1451.36,2667.86 r180 top value=4.7uF
C41 "GCM188R71C105KA64J" 0603L 1408.98,3115.04 r270 top value=1uF
C42 "CGA3E2X7R1E104K080AA" 0603 1755,3124.29 r180 top value=0.1uF
C43 "GCM1885C2A101JA16D" 0603 1698.06,2835.46 r270 top value=100pF
C44 "CGA3E2X7R1E104K080AA" 0603 1244.59,2685.57 r0 top value=0.1uF
C45 "GCJ32DC72A475KE01L" FP-GCJ32DC72A475KE01L_1210-MFG 840.11,2264.55 r90 bottom value=4.7µF
C46 "GCJ32DC72A475KE01L" FP-GCJ32DC72A475KE01L_1210-MFG 958.56,2264.53 r90 bottom value=4.7µF
C47 "GCJ32DC72A475KE01L" FP-GCJ32DC72A475KE01L_1210-MFG 957.42,2444.13 r270 bottom value=4.7µF
C48 "GCJ32DC72A475KE01L" FP-GCJ32DC72A475KE01L_1210-MFG 839.65,2442.09 r270 bottom value=4.7µF
C49 "CGA3E2X7R1E104K080AA" 0603 853.45,2389.31 r270 top value=0.1uF
C50 "CGA3E2X7R1E104K080AA" 0603 946.06,2388.46 r270 top value=0.1uF
C51 "CL21B224KCFSNWE" 0805 1040.14,2237.89 r270 top value=0.22uF
C52 "CL21B224KCFSNWE" 0805 1127.74,2237.04 r270 top value=0.22uF
C53 "GCM21BC71E475KE36L" 0805_HV 418.69,2151.79 r180 top value=4.7uF
C54 "GCM155R71C104JA55D" 0402 586.97,2151.79 r0 top value=0.1uF
C55 "CGA3E2X7R1E104K080AA" 0603 1335.42,3146.17 r270 top value=0.1uF
C56 "GCM155R71C104JA55D" 0402 616.11,2329.94 r0 top value=0.1uF
C57 "CGA3E2X7R2A102K080AA" 0603 2404.43,801.83 r270 top value=1000pF
C58 "GRM188R72A103KA01D" 0603 2337.85,801.49 r90 top value=0.01uF
C59 "CGA3E2X7R1E104K080AA" 0603 2473.21,801.33 r90 top value=0.1uF
C60 "CGA6P3X7R1E226M250AB" FP-CGA6P3X7R1E226M250AB_1210-MFG 885.34,1209.09 r90 top value=22µF
C61 "CGA6P3X7R1E226M250AB" FP-CGA6P3X7R1E226M250AB_1210-MFG 1005.56,1208.82 r90 top value=22µF
C62 "CGA6P3X7R1E226M250AB" FP-CGA6P3X7R1E226M250AB_1210-MFG 1130.77,1208.7 r90 top value=22µF
C63 "CGA6P3X7R1E226M250AB" FP-CGA6P3X7R1E226M250AB_1210-MFG 1248.66,1208.7 r90 top value=22µF
C64 "CGA6P3X7R1E226M250AB" FP-CGA6P3X7R1E226M250AB_1210-MFG 1370.37,1208.7 r90 top value=22µF
C65 "TCQE157M016R0025E" FP-TCQE157M016R0025E_2917-MFG 805.73,1018.3 r270 bottom value=150µF
C66 "TCQE157M016R0025E" FP-TCQE157M016R0025E_2917-MFG 1195,1020 r270 bottom value=150µF
C67 "TCQE157M016R0025E" FP-TCQE157M016R0025E_2917-MFG 999.28,1018.3 r270 bottom value=150µF
C68 "UMK107AB7105KA-T" 0603 651.15,1652.79 r90 top value=1uF
C69 "GCM1885C2A101JA16D" 0603 1191.39,2869.66 r270 top value=100pF
C70 "CGA3E2C0G1H100D080AA" 0603 1575.88,3277.89 r90 top value=10pF
C71 "GCM188R71H103KA37D" 0603 1650.85,3279.19 r90 top value=0.01uF
C72 "CGA6P3X7R1E226M250AB" FP-CGA6P3X7R1E226M250AB_1210-MFG 1487.81,1208.28 r90 top value=22µF
C73 "CGA6P3X7R1E226M250AB" FP-CGA6P3X7R1E226M250AB_1210-MFG 1605.02,1210 r90 top value=22µF
C74 "CGA6P3X7R1E226M250AB" FP-CGA6P3X7R1E226M250AB_1210-MFG 1724.8,1210.83 r90 top value=22µF
C75 "CGA3E2X7R1E104K080AA" 0603 2208.51,238.78 r90 bottom value=0.1uF
C76 "CGA6P3X7R1E226M250AB" FP-CGA6P3X7R1E226M250AB_1210-MFG 1848.78,1210 r90 top value=22µF
C77 "CGA3E2X7R1E104K080AA" 0603 1798.34,2867.84 r180 top value=0.1uF
C78 "CGA3E2X7R1E104K080AA" 0603 1093.1,2901.15 r0 top value=0.1uF
C79 "CGA6P3X7R1E226M250AB" FP-CGA6P3X7R1E226M250AB_1210-MFG 2683.4,1210.67 r90 top value=22µF
C80 "CGA6P3X7R1E226M250AB" FP-CGA6P3X7R1E226M250AB_1210-MFG 2801,1210.07 r90 top value=22µF
C81 "CGA6P3X7R1E226M250AB" FP-CGA6P3X7R1E226M250AB_1210-MFG 2564.59,1210.07 r90 top value=22µF
C82 "CGA6P3X7R1E226M250AB" FP-CGA6P3X7R1E226M250AB_1210-MFG 527.34,1208.36 r90 top value=22µF
C83 "CGA6P3X7R1E226M250AB" FP-CGA6P3X7R1E226M250AB_1210-MFG 645.69,1209.44 r90 top value=22µF
C84 "CGA6P3X7R1E226M250AB" FP-CGA6P3X7R1E226M250AB_1210-MFG 764.22,1210.06 r90 top value=22µF
"CAUTION HOT SURFACE1" "CAUTION HOT SURFACE" IEC_HotSurface_Small 3050,1900 r0 top
FID1 "Fiducial" Fiducial10-20 3444.88,167.26 r0 top
FID2 "Fiducial" Fiducial10-20 452.76,165.43 r0 top
FID3 "Fiducial" Fiducial10-20 560.54,3714.88 r0 top
GND1 "GND_IN" Keystone5011 3305.76,2946.15 r0 top
H1 "NY PMS 440 0025 PH" "NY PMS 440 0025 PH" 3737.01,200 r0 top locked
H2 "NY PMS 440 0025 PH" "NY PMS 440 0025 PH" 200,200 r0 top locked
H3 "NY PMS 440 0025 PH" "NY PMS 440 0025 PH" 285.43,3700.79 r0 top locked
H4 "NY PMS 440 0025 PH" "NY PMS 440 0025 PH" 2726.62,3700.14 r0 top locked
H5 "1902C" Keystone_1902C 3737.01,200 r180 bottom locked
H6 "1902C" Keystone_1902C 200,200 r180 bottom locked
H7 "1902C" Keystone_1902C 285.43,3700.79 r180 bottom locked
H8 "1902C" Keystone_1902C 2726.62,3700.14 r180 bottom locked
J1 "EM292902-UL" Eaton_EM292902 3514.65,3509.49 r180 top
J2 "EM292902-UL" Eaton_EM292902 1629.53,614.98 r0 top
J3 "TSW-114-07-G-S" TSW-114-07-G-S 1603.51,3689.57 r0 top
J4 "5-146261-1" CONN_5-146261-1 3011.7,581.76 r90 top
J5 "MMCX-J-P-H-ST-TH1" Samtec_MMCX-J-P-H-ST-TH1 2192.05,462.32 r0 top
J6 "MMCX-J-P-H-ST-TH1" Samtec_MMCX-J-P-H-ST-TH1 2191.17,721.12 r0 top
L1 "VCHA105D-1R0MS6" VCHA105D 3560.71,1386.05 r180 bottom value=1uH
L2 "7448421016" WE-CMB_NiZn_S 3543.31,2272.21 r270 bottom value=16uH
L4 "VCUD128T-2R5MS8" FP-VCUD128T-2R5MS8_SMT_IND_13MM3_12MM8-MFG 2221.16,1666.59 r270 top value=2.5uH
L6 "" FP-VCUD128T-2R5MS8_SMT_IND_13MM3_12MM8-MFG 1077.4,1678.98 r270 top value=2.5uH
LBL1 "THT-14-423-10" Label_650x200 3502.9,876.83 r0 top
Logo1 "CE Mark" CE_Mark_5mm 296.41,3250 r0 top
Logo2 "Texas Instruments" TI_Stacked_Overlay_Small 725,725 r0 top
Logo3 "FCC disclaimer" FCC_disclaimer 1853.51,3754.09 r0 top
Logo4 "WEEE logo" WEEE_Minimum 625,3290.07 r0 top
NT1 "Net-Tie" Net-Tie_10mil 2550.58,1634.67 r180 top net-tie
NT2 "Net-Tie" Net-Tie_10mil 689.36,1646.64 r0 top net-tie
NT3 "Net-Tie" Net-Tie_10mil 1456.05,2956.02 r90 top net-tie
PGND1 "PGND" Keystone5011 2117.69,160 r0 top
Q1 "CSD17570Q5B" DNK0008A 2719.98,547.27 r90 bottom value=30V
Q2 "CSD17570Q5B" DNK0008A 2438.28,547.17 r90 bottom value=30V
R1 "RCL12251R00FKEG" FP-RCL12251R00FKEG_2512-MFG 3257.87,1067.86 r90 bottom value=1
R2 "CRCW04022R20JNED" 0402 1719.56,2188.44 r0 top value=2.2
R3 "CRCW04022R20JNED" 0402 1815.41,2294.46 r180 top value=2.2
R4 "RC1210FR-072K49L" 1210 2605.7,1817.26 r270 top value=2.49k
R5 "CRCW06030000Z0EAHP" FP-CRCW06030000Z0EAHP_0603-MFG 1752.2,2061.51 r0 bottom value=0
R6 "CRCW06030000Z0EAHP" FP-CRCW06030000Z0EAHP_0603-MFG 1770.08,1946.74 r90 bottom value=0
R7 "CRCW06030000Z0EAHP" FP-CRCW06030000Z0EAHP_0603-MFG 1847.63,1946.52 r90 bottom value=0
R8 "CRCW06030000Z0EAHP" FP-CRCW06030000Z0EAHP_0603-MFG 1925.3,1946.78 r90 bottom value=0
R9 "NCU18WB473J6SRB" FP-NCU18WB473J6SRB_0603-MFG 2707.41,1602.18 r180 top value=47kΩ
R10 "CRCW06030000Z0EA" 0603 1620.95,2614.29 r180 top value=0
R11 "CRCW06030000Z0EAHP" FP-CRCW06030000Z0EAHP_0603-MFG 1853.43,2442.26 r270 bottom value=0
R12 "CRCW06032K00FKEA" 0603 2706,1669.46 r180 top value=2.00k
R13 "RCS06030000Z0EA" 0603 2704.12,1533.06 r180 top value=0
R14 "CRCW06030000Z0EAHP" FP-CRCW06030000Z0EAHP_0603-MFG 1759.12,2385.59 r0 bottom value=0
R15 "CRCW06034K70JNEA" 0603 1708.33,2053.09 r180 top value=4.7k
R16 "CRCW060310K0FKEA" 0603 1754.85,3191.69 r0 top value=10.0k
R17 "ERJ-3EKF49R9V" 0603 1729.08,2803.92 r0 bottom value=49.9
R18 "ERA-3AEB1403V" 0603 1699.19,2927.38 r0 bottom value=140k
R19 "CRCW060310K0FKEA" 0603L 1700.93,2954.38 r0 top value=10.0k
R20 "CRCW06030000Z0EA" 0603 1246.41,2614.22 r0 top value=0
R21 "CRCW04022R20JNED" 0402 585.97,2203.19 r0 top value=2.2
R22 "CRCW060341K2FKEA" 0603 1699.09,3065.28 r180 top value=41.2k
R23 "CRCW060320K0FKEA" 0603S 1526.32,3112.85 r270 top value=20.0k
R24 "CRCW060352K3FKEA" 0603L 1476.9,3115.04 r270 top value=52.3k
R25 "CRCW060310K0FKEA" 0603 1244.86,3146.17 r90 top value=10.0k
R26 "CRCW04022R20JNED" 0402 615.27,2278.23 r180 top value=2.2
R27 "RC1210FR-072K49L" 1210 648.17,1825 r270 top value=2.49k
R28 "CRCW060310K0FKEA" 0603 1411.99,3090.75 r180 bottom value=10.0k
R29 "CRCW06030000Z0EAHP" FP-CRCW06030000Z0EAHP_0603-MFG 614.1,2074.19 r0 bottom value=0
R30 "CRCW06030000Z0EAHP" FP-CRCW06030000Z0EAHP_0603-MFG 692.68,1999.64 r90 bottom value=0
R31 "CRCW06030000Z0EAHP" FP-CRCW06030000Z0EAHP_0603-MFG 771.08,1999.44 r90 bottom value=0
R32 "CRCW06030000Z0EAHP" FP-CRCW06030000Z0EAHP_0603-MFG 850.36,1999.08 r90 bottom value=0
R33 "NCU18WB473J6SRB" FP-NCU18WB473J6SRB_0603-MFG 533.29,1621.33 r0 top value=47kΩ
R34 "CRCW06030000Z0EAHP" FP-CRCW06030000Z0EAHP_0603-MFG 704.79,2438.36 r270 bottom value=0
R35 "CRCW06032K00FKEA" 0603 530.22,1686.62 r0 top value=2.00k
R36 "RCS06030000Z0EA" 0603 530.22,1547.45 r0 top value=0
R37 "CRCW060349R9FKEA" 0603L 1836.84,2950.95 r270 bottom value=49.9
R38 "CRCW06030000Z0EAHP" FP-CRCW06030000Z0EAHP_0603-MFG 611.63,2395.9 r0 bottom value=0
R39 "CRCW06034K70JNEA" 0603 575.98,2092.97 r180 top value=4.7k
R40 "CRCW0603191KFKEA" 0603 976.22,3536.26 r270 bottom value=191k
R41 "CRCW0603100KFKEA" 0603L 1353.76,3805.58 r90 bottom value=100k
R42 "CRCW0603100KFKEA" 0603L 1553.51,3802.78 r90 bottom value=100k
R43 "CRCW0603100KFKEA" 0603L 1655.28,3805.58 r90 bottom value=100k
R44 "ERJ-3EKF49R9V" 0603 1163.15,2838.42 r180 bottom value=49.9
R45 "ERA-3AEB1403V" 0603 1698.94,3007.42 r0 bottom value=140k
R46 "CRCW060348K7FKEA" 0603 1698.94,3098.93 r0 bottom value=48.7k
R47 "CRCW06034K99FKEA" 0603 1051.93,3536.26 r270 bottom value=4.99k
R48 "CRCW060310K0FKEA" 0603L 1700.93,3009.67 r0 top value=10.0k
R49 "CRCW060338K3FKEA" 0603 1614.55,3166.84 r180 top value=38.3k
R50 "CRCW060310K0FKEA" 0603 901.41,3536.26 r270 bottom value=10.0k
R51 "CRCW060310K0FKEA" 0603 1950.73,3585.72 r0 bottom value=10.0k
R52 "CRCW06031R00JNEA" 0603 2896.22,483.97 r270 bottom value=1.0
R53 "CRCW06031R00JNEA" 0603 2579.93,305.91 r90 bottom value=1.0
R54 "CRCW060310K0FKEA" 0603 2896.59,617.23 r270 bottom value=10.0k
R55 "CRCW060349R9FKEA" 0603 2136.15,303.31 r90 bottom value=49.9
R56 "CRCW060349R9FKEA" 0603 2302.01,839.53 r0 bottom value=49.9
R57 "WK73S3ATTER200F" FP-WK73S3ATTER200F_1225-MFG 2404.1,289.71 r90 bottom value=0.2
R58 "WK73S3ATTER200F" FP-WK73S3ATTER200F_1225-MFG 2753.86,289.71 r90 bottom value=0.2
R59 "CRCW06034K99FKEA" 0603 1154.68,3540.16 r270 bottom value=4.99k
R60 "CRCW0603191KFKEA" 0603 1232.32,3540.16 r270 bottom value=191k
R61 "CRCW060310K0FKEA" 0603 1305.34,3540.48 r270 bottom value=10.0k
R62 "RC1210FR-072K49L" 1210 2761.83,1817.26 r270 top value=2.49k
R63 "RC1210FR-072K49L" 1210 479.59,1825 r270 top value=2.49k
R64 "CRCW060310K0FKEA" 0603 1586.81,3568.98 r180 bottom value=10.0k
R65 "CRCW060310K0FKEA" 0603 1952.65,3477.23 r0 bottom value=10.0k
RT1 "TMP6131QDYARQ1" DYA0002A-MFG 2203.72,2088.64 r180 top value=10kΩ
RT2 "TMP6131QDYARQ1" DYA0002A-MFG 1054.18,2108.93 r180 top value=10kΩ
U1 "LMG2100R026VBNR" VBN0016A-MFG 1985.94,2168.69 r90 top
U2 "LM5137FDQRHARQ1" RHA0036D-MFG 1446.21,2870.63 r0 top
U3 "LMG2100R026VBNR" VBN0016A-MFG 841.26,2183.18 r90 top
VIN1 "VIN" Keystone5010 3731.24,2946.15 r0 top
VOUT_BODE "VOUT" Keystone5010 2145.57,3180.17 r90 top
VOUT_PWR1 "VOUT" Keystone5010 855.62,378.45 r90 top
ZZ1 "This Assembly Note is for PCB labels only" AssemblyNoteLabel 0,4337.01 r0 top
ZZ2 "These assemblies are ESD sensitive, ESD precautions shall be observed." AssemblyNote 0,4237.01 r0 top
ZZ3 "These assemblies must be clean and free from flux and all contaminants. Use of no clean flux is not acceptable." AssemblyNote 0,4137.01 r0 top
ZZ4 "These assemblies must comply with workmanship standards IPC-A-610 Class 2, unless otherwise specified." AssemblyNote 0,4037.01 r0 top

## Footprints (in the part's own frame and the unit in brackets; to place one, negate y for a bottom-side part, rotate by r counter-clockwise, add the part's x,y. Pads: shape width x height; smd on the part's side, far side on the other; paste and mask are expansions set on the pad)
0402 [mm] "0402 from SM-752 data"
  rect 0.8x0.6 smd: 1(-0.6,0) 2(0.6,0)
  silkscreen extent -1.22,-0.52 1.22,0.52, body extent -0.55,-0.3 0.55,0.3, height 0.6
0603 [mm] "0603 from SM-752 data"
  rect 1x0.95 smd: 1(-0.8,0) 2(0.8,0)
  silkscreen extent -1.52,-0.69 1.52,0.69, body extent -0.87,-0.47 0.87,0.47, height 1
0603L [mm] "0603 from SM-752 data"
  rect 0.8x0.85 smd: 1(-0.7,0) 2(0.7,0)
  silkscreen extent -0.07,-0.33 0.07,0.33, body extent -0.87,-0.47 0.87,0.47, height 1
0603S [mil]
  rect 20x35 smd: 1(-30,0) 2(30,0)
  body extent -34,-19 34,19, height 39
0805 [mm] "0805 from SM-752 data"
  rect 1.3x1.5 smd: 1(-0.85,0) 2(0.85,0)
  silkscreen extent -1.72,-0.97 1.72,0.97, body extent -1.1,-0.72 1.1,0.72, height 1.45
0805_HV [mil] "0805 with 30mil clearance between pads"
  rect 50x63 smd: 1(-40,0) 2(40,0)
  silkscreen extent -74,-40 74,40, body extent -43,-29 43,29, height 57
1210 [mm] "1210 from SM-752 data"
  rect 1.3x2.7 smd: 1(-1.45,0) 2(1.45,0)
  silkscreen extent -2.32,-1.57 2.32,1.57, body extent -1.7,-1.35 1.7,1.35, height 1.35
AssemblyNote [mil] "Assembly Note"
AssemblyNoteLabel [mil] "Assembly Note for PCB Labels"
CE_Mark_5mm [mil] "Minimum text height for CE Mark"
  silkscreen extent -138,-98 138,98
CONN_5-146261-1 [mm] "Sullins"
  rect 1.5x1.5 hole 1.02: 1(-1.27,0)
  round 1.5 hole 1.02: 2(1.27,0)
  silkscreen extent -3.68,-1.27 2.54,1.27, body extent -2.51,-1.27 2.51,1.27, height 10.87
DNK0008A [mm] "SON, 8-Leads, Body 5x6mm"
  rrect39% 0.86x0.51 smd paste-0.05 mask-0.05: 1(-2.82,1.905) 2(-2.82,0.635) 3(-2.82,-0.635) 4(-2.82,-1.905) 5(2.82,-1.905) 6(2.82,-0.635) 7(2.82,0.635) 8(2.82,1.905)
  rrect40% 0.25x0.555 on Bottom Paste: 9(-0.83,-2.372) 9(-0.83,2.372)
  rrect40% 0.25x0.555 on Bottom Solder: 9(-0.83,-2.372) 9(-0.83,2.372)
  rrect11% 0.95x1.13 on Bottom Paste: 9(-0.535,-1.33) 9(-0.535,0) 9(-0.535,1.33) 9(0.615,-1.33) 9(0.615,0) 9(0.615,1.33) 9(1.765,-1.33) 9(1.765,0) 9(1.765,1.33)
  rrect3% 3.58x4 on Bottom Solder: 9(0.75,0)
  rrect5% 4.34x5.4 smd paste-3 mask-3: 9(1.08,0)
  body extent -3.05,-2.55 3.05,2.55, height 1.06
DYA0002A-MFG [mm]
  rrect25% 0.67x0.4 smd paste+0 mask+0: 1(-0.74,0) 2(0.74,0)
  silkscreen extent -1.75,-0.63 0.65,0.63, body extent -1.17,-0.67 1.17,0.67, height 0.25
Eaton_EM292902 [mm] "Terminal Block, 10.16mm, 2x1, TH"
  round 2.6 hole 1.7 paste-2539.97 mask+0: 1(-5.08,7.48) 2(5.08,7.48) 2(5.08,-2.68)
  rrect4% 2.6x2.6 hole 1.7 paste-2539.97 mask+0: 1(-5.08,-2.68)
  round 2 hole 2 unplated paste-2539.97 mask+0: ""(0,4.7) ""(0,0) ""(0,-4.5)
  silkscreen extent -10.17,-10.02 10.17,9.98, body extent -10.27,-10.12 10.27,10.08, height 0.25
FCC_disclaimer [mil]
Fiducial10-20 [mm]
  round 1 smd mask+0.5: 1(0,0)
  Top Layer keep-out circle w1.178: c0,0 r0.5
FP-CGA6P3X7R1E226M250AB_1210-MFG [mm]
  rrect9% 1.1x2.2 smd paste+0 mask+0: 1(-1.65,0) 2(1.65,0)
  silkscreen extent -0.72,-1.4 0.72,1.4, body extent -1.6,-1.25 1.6,1.25, height 2.81
FP-CRCW06030000Z0EAHP_0603-MFG [mm]
  rrect13% 0.75x1 smd paste+0 mask+0: 1(-0.75,0) 2(0.75,0)
  silkscreen extent -0.8,-0.9 0.8,0.9, body extent -0.8,-0.43 0.8,0.43, height 0.55
FP-GCJ32DC72A475KE01L_1210-MFG [mm]
  rrect9% 1.1x2.05 smd paste+0 mask+0: 1(-1.65,0) 2(1.65,0)
  silkscreen extent -1.8,-1.4 1.8,1.4, body extent -1.6,-1.25 1.6,1.25, height 2.3
FP-NCU18WB473J6SRB_0603-MFG [mm]
  rrect15% 0.65x0.7 smd paste+0 mask+0: 1(-0.775,0) 2(0.775,0)
  silkscreen extent -0.87,-0.72 0.87,0.72, body extent -0.8,-0.4 0.8,0.4, height 0.95
FP-RCL12251R00FKEG_2512-MFG [mm]
  rrect6% 1.6x6.6 smd paste+0 mask+0: 1(-1.4,0) 2(1.4,0)
  silkscreen extent -0.23,-3.25 0.23,3.25, body extent -1.6,-3.15 1.6,3.15, height 0.8
FP-TCME227M016R0025E_2917-MFG [mm]
  rrect5% 2x3 smd paste+0 mask+0: 1(-3,0) 2(3,0)
  silkscreen extent -3.75,-2.25 4.87,2.25, body extent -3.65,-2.15 3.65,2.15, height 4.3
FP-TCQE157M016R0025E_2917-MFG [mm] "Recommended Land Pattern"
  rrect5% 2x3 smd paste+0 mask+0: 1(-3,0) 2(3,0)
  silkscreen extent -3.75,-2.25 4.87,2.25, body extent -3.65,-2.15 3.65,2.15, height 4.3
FP-VCUD128T-2R5MS8_SMT_IND_13MM3_12MM8-MFG [mm]
  rrect3% 4x13.2 smd paste+0 mask+0: 1(-5.35,0) 2(5.35,0)
  silkscreen extent -2.98,-6.55 6.94,9.24, body extent -6.65,-6.4 6.65,6.4, height 8
FP-WK73S3ATTER200F_1225-MFG [mm] "Recommended Land Pattern"
  rrect9% 1.15x6.4 smd paste+0 mask+0: 1(-1.375,0) 2(1.375,0)
  silkscreen extent -0.43,-3.22 0.43,3.22, body extent -1.55,-3.15 1.55,3.15, height 0.7
IEC_HotSurface_Small [mil]
  silkscreen extent -107,-93 107,92
Keystone5010 [mil] "Keystone Multipurpose loops"
  round 87 hole 63: 1(0,0)
  silkscreen extent -70,-70 70,70, body extent -63,-63 62,62, height 319
Keystone5011 [mil] "Keystone Multipurpose loops"
  round 87 hole 63: 1(0,0)
  silkscreen extent -70,-70 70,70, body extent -63,-63 63,62, height 319
Keystone5012 [mil] "Keystone Multipurpose loops"
  round 87 hole 63: 1(0,0)
  silkscreen extent -70,-70 70,70, body extent -63,-63 63,62, height 319
Keystone_1902C [mil] "Hex Standoff, 4-40 threaded, nylon"
  round 1 on Mech4: 0(0,0)
  body extent -145,-126 146,126, height 501
Label_650x200 [mil] "Thermal Transfer Label"
  round 1 on Mech13: 0(0,0)
  silkscreen extent -325,-100 325,100, body extent -325,-100 325,100, height 1
Net-Tie_10mil [mil] "10mil net tie, no solder mask opening, no solder paste"
  rect 10x10 smd paste-5 mask-5: 1(-10,0) 2(10,0)
  Top Layer region: -6,5 6,5 6,-5 -6,-5
"NY PMS 440 0025 PH" [mm] "4-40 nylon screw and mounting hole"
  round 8 hole 3.2: 1(0,0)
  body extent -3.3,-3.3 3.3,3.3, height 2.69
RHA0036D-MFG [mm]
  rrect40% 0.6x0.25 smd paste+0 mask+0: 1(-2.9,2.25) 2(-2.9,1.75) 3(-2.9,0.75) 4(-2.9,0.25) 5(-2.9,-0.25) 6(-2.9,-0.75) 7(-2.9,-1.25) 8(-2.9,-1.75) 9(-2.9,-2.25) 18(2.9,-2.25) 19(2.9,-1.75) 20(2.9,-1.25) 21(2.9,-0.75) 22(2.9,-0.25) 23(2.9,0.25) 24(2.9,1.25) 25(2.9,1.75) 26(2.9,2.25)
  rrect40% 0.25x0.6 smd paste+0 mask+0: 10(-2.25,-2.9) 11(-1.75,-2.9) 12(-0.75,-2.9) 13(-0.25,-2.9) 14(0.25,-2.9) 15(0.75,-2.9) 16(1.75,-2.9) 17(2.25,-2.9) 27(2.25,2.9) 28(1.75,2.9) 29(1.25,2.9) 30(0.75,2.9) 31(0.25,2.9) 32(-0.25,2.9) 33(-0.75,2.9) 34(-1.25,2.9) 35(-1.75,2.9) 36(-2.25,2.9)
  rrect3% 3.3x3.3 smd paste-1000 mask+0: 37(0,0)
  silkscreen extent -3.87,-3.05 3.05,3.05, body extent -3.3,-3.3 3.3,3.3, height 0.25
Samtec_MMCX-J-P-H-ST-TH1 [mm] "Connector, MMCX, TH"
  round 1.2 hole 0.84: 1(0,0) 2(-1.27,1.27) 3(1.27,1.27) 4(1.27,-1.27) 5(-1.27,-1.27)
  silkscreen extent -1.75,-1.75 1.75,1.75, body extent -1.75,-1.75 1.75,1.75, height 4.35
SM_RADIAL_H13 [mm] "12.5 x 13.5mm:  Panasonic H13"
  rect 5.7x2 smd: 1(-4.85,0) 2(4.85,0)
  silkscreen extent -6.85,-6.85 6.85,6.85, body extent -6.85,-6.85 6.85,6.85, height 14
TI_Stacked_Overlay_Small [mil]
  silkscreen extent -418,-98 418,98
TSW-114-07-G-S [mm] "Samtec 100mil, 1x14, 230 mil above insulator"
  rrect6% 1.65x1.65 hole 1.016: 1(-16.51,0)
  round 1.65 hole 1.016: 2(-13.97,0) 3(-11.43,0) 4(-8.89,0) 5(-6.35,0) 6(-3.81,0) 7(-1.27,0) 8(1.27,0) 9(3.81,0) 10(6.35,0) 11(8.89,0) 12(11.43,0) 13(13.97,0) 14(16.51,0)
  silkscreen extent -17.78,-1.27 17.78,1.27, body extent -17.78,-1.27 17.78,1.27, height 8.38
VBN0016A-MFG [mm]
  round 0.228 smd paste+0 mask+0: 1(-1.925,3.125) 11(1.925,3.125)
  rrect40% 0.7x0.25 smd paste+0 mask+0: 2(-2.1,2.575) 3(-2.1,2.075) 4(-2.1,1.575) 8(2.1,1.575) 9(2.1,2.075) 10(2.1,2.575)
  round 0.394 smd paste+0 mask+0: 5(-1.969,-1.335) 7(1.969,-1.335)
  rrect8% 2.35x1.33 smd paste-1000 mask+0: 6(-0.225,1.985)
  round 1.603 smd paste-1000 mask+0: 6(-0.059,-2.453)
  rrect5% 1.9x1.976 smd paste-1000 mask+0: 6(0,0.032)
  rrect40% 0.25x0.7 smd paste+0 mask+0: 12(0.825,3.35) 13(0.325,3.35) 14(-0.175,3.35) 15(-0.675,3.35) 16(-1.175,3.35)
  Top Layer region: 2.4,2.95 2.419,2.954 2.435,2.965 2.446,2.981 2.45,3 2.45,3 2.45,3.15 2.446,3.169 2.435,3.185 2.419,3.196 2.4,3.2 2.4,3.2 2.05,3.2 2.025,3.207 2.007,3.225 2,3.25 2,3.25 2,3.65 1.996,3.669 1.985,3.685 1.969,3.696 1.95,3.7 1.95,3.7 1.8,3.7 1.781,3.696 1.765,3.685 1.754,3.669 1.75,3.65 1.75,3.65 1.75,3 1.754,2.981 1.765,2.965 1.781,2.954 1.8,2.95 1.8,2.95
  Top Layer region: -2.4,2.95 -2.419,2.954 -2.435,2.965 -2.446,2.981 -2.45,3 -2.45,3 -2.45,3.15 -2.443,3.175 -2.425,3.193 -2.4,3.2 -2.4,3.2 -2.05,3.2 -2.031,3.204 -2.015,3.215 -2.004,3.231 -2,3.25 -2,3.25 -2,3.65 -1.993,3.675 -1.975,3.693 -1.95,3.7 -1.95,3.7 -1.8,3.7 -1.781,3.696 -1.765,3.685 -1.754,3.669 -1.75,3.65 -1.75,3.65 -1.75,3 -1.754,2.981 -1.765,2.965 -1.781,2.954 -1.8,2.95 -1.8,2.95
  Top Layer region: -0.55,-3.65 -0.554,-3.669 -0.565,-3.685 -0.581,-3.696 -0.6,-3.7 -0.6,-3.7 -0.75,-3.7 -0.775,-3.693 -0.793,-3.675 -0.8,-3.65 -0.8,-3.65 -0.8,-3.425 -0.804,-3.406 -0.815,-3.39 -0.831,-3.379 -0.85,-3.375 -0.85,-3.375 -0.9,-3.375 -0.925,-3.368 -0.943,-3.35 -0.95,-3.325 -0.95,-3.325 -0.95,-1.506 -0.943,-1.481 -0.925,-1.463 -0.9,-1.456 -0.9,-1.456 0.9,-1.456 0.919,-1.46 0.935,-1.471 0.946,-1.487 0.95,-1.506 0.95,-1.506 0.95,-3.325 0.943,-3.35 0.925,-3.368 0.9,-3.375 0.9,-3.375 0.5,-3.375 0.481,-3.379 0.465,-3.39 0.454,-3.406 0.45,-3.425 0.45,-3.425 0.45,-3.65 0.443,-3.675 0.425,-3.693 0.4,-3.7 0.4,-3.7 0.25,-3.7 0.231,-3.696 0.215,-3.685 0.204,-3.669 0.2,-3.65 0.2,-3.65 0.2,-3.425 0.196,-3.406 0.185,-3.39 0.169,-3.379 0.15,-3.375 0.15,-3.375 0,-3.375 -0.019,-3.379 -0.035,-3.39 -0.046,-3.406 -0.05,-3.425 -0.05,-3.425 -0.05,-3.65 -0.054,-3.669 -0.065,-3.685 -0.081,-3.696 -0.1,-3.7 -0.1,-3.7 -0.25,-3.7 -0.275,-3.693 -0.293,-3.675 -0.3,-3.65 -0.3,-3.65 -0.3,-3.425 -0.304,-3.406 -0.315,-3.39 -0.331,-3.379 -0.35,-3.375 -0.35,-3.375 -0.5,-3.375 -0.519,-3.379 -0.535,-3.39 -0.546,-3.406 -0.55,-3.425 -0.55,-3.425
  Top Layer region: 2.075,0.542 2.094,0.538 2.11,0.527 2.121,0.511 2.125,0.492 2.125,0.492 2.125,0.338 2.129,0.319 2.14,0.303 2.156,0.292 2.175,0.288 2.175,0.288 2.4,0.288 2.419,0.284 2.435,0.273 2.446,0.257 2.45,0.238 2.45,0.238 2.45,0.088 2.443,0.063 2.425,0.045 2.4,0.038 2.4,0.038 2.175,0.038 2.156,0.034 2.14,0.023 2.129,0.007 2.125,-0.012 2.125,-0.012 2.125,-0.162 2.132,-0.187 2.15,-0.205 2.175,-0.212 2.175,-0.212 2.4,-0.212 2.425,-0.219 2.443,-0.237 2.45,-0.262 2.45,-0.262 2.45,-0.412 2.446,-0.431 2.435,-0.447 2.419,-0.458 2.4,-0.462 2.4,-0.462 2.175,-0.462 2.156,-0.466 2.14,-0.477 2.129,-0.493 2.125,-0.512 2.125,-0.512 2.125,-0.662 2.129,-0.681 2.14,-0.697 2.156,-0.708 2.175,-0.712 2.175,-0.712 2.4,-0.712 2.419,-0.716 2.435,-0.727 2.446,-0.743 2.45,-0.762 2.45,-0.762 2.45,-0.912 2.446,-0.931 2.435,-0.947 2.419,-0.958 2.4,-0.962 2.4,-0.962 2.175,-0.962 2.156,-0.966 2.14,-0.977 2.129,-0.993 2.125,-1.012 2.125,-1.012 2.125,-1.162 2.129,-1.181 2.14,-1.197 2.156,-1.208 2.175,-1.212 2.175,-1.212 2.4,-1.212 2.419,-1.216 2.435,-1.227 2.446,-1.243 2.45,-1.262 2.45,-1.262 2.45,-1.412 2.446,-1.431 2.435,-1.447 2.419,-1.458 2.4,-1.462 2.4,-1.462 2.175,-1.462 2.156,-1.466 2.14,-1.477 2.129,-1.493 2.125,-1.512 2.125,-1.512 2.125,-1.662 2.129,-1.681 2.14,-1.697 2.156,-1.708 2.175,-1.712 2.175,-1.712 2.4,-1.712 2.419,-1.716 2.435,-1.727 2.446,-1.743 2.45,-1.762 2.45,-1.762 2.45,-1.912 2.446,-1.931 2.435,-1.947 2.419,-1.958 2.4,-1.962 2.4,-1.962 2.175,-1.962 2.156,-1.966 2.14,-1.977 2.129,-1.993 2.125,-2.012 2.125,-2.012 2.125,-2.162 2.129,-2.181 2.14,-2.197 2.156,-2.208 2.175,-2.212 2.175,-2.212 2.4,-2.212 2.419,-2.216 2.435,-2.227 2.446,-2.243 2.45,-2.262 2.45,-2.262 2.45,-2.412 2.446,-2.431 2.435,-2.447 2.419,-2.458 2.4,-2.462 2.4,-2.462 2.175,-2.462 2.156,-2.466 2.14,-2.477 2.129,-2.493 2.125,-2.512 2.125,-2.512 2.125,-2.662 2.129,-2.681 2.14,-2.697 2.156,-2.708 2.175,-2.712 2.175,-2.712 2.4,-2.712 2.419,-2.716 2.435,-2.727 2.446,-2.743 2.45,-2.762 2.45,-2.762 2.45,-2.912 2.446,-2.931 2.435,-2.947 2.419,-2.958 2.4,-2.962 2.4,-2.962 2.175,-2.962 2.156,-2.966 2.14,-2.977 2.129,-2.993 2.125,-3.012 2.125,-3.012 2.125,-3.166 2.121,-3.185 2.11,-3.201 2.094,-3.212 2.075,-3.216 2.075,-3.216 1.8,-3.216 1.775,-3.209 1.757,-3.191 1.75,-3.166 1.75,-3.166 1.75,0.492 1.754,0.511 1.765,0.527 1.781,0.538 1.8,0.542 1.8,0.542
  Top Layer region: -2.075,0.542 -2.1,0.535 -2.118,0.517 -2.125,0.492 -2.125,0.492 -2.125,0.338 -2.129,0.319 -2.14,0.303 -2.156,0.292 -2.175,0.288 -2.175,0.288 -2.4,0.288 -2.425,0.281 -2.443,0.263 -2.45,0.238 -2.45,0.238 -2.45,0.088 -2.443,0.063 -2.425,0.045 -2.4,0.038 -2.4,0.038 -2.175,0.038 -2.15,0.031 -2.132,0.013 -2.125,-0.012 -2.125,-0.012 -2.125,-0.162 -2.132,-0.187 -2.15,-0.205 -2.175,-0.212 -2.175,-0.212 -2.4,-0.212 -2.419,-0.216 -2.435,-0.227 -2.446,-0.243 -2.45,-0.262 -2.45,-0.262 -2.45,-0.412 -2.443,-0.437 -2.425,-0.455 -2.4,-0.462 -2.4,-0.462 -2.175,-0.462 -2.156,-0.466 -2.14,-0.477 -2.129,-0.493 -2.125,-0.512 -2.125,-0.512 -2.125,-0.662 -2.129,-0.681 -2.14,-0.697 -2.156,-0.708 -2.175,-0.712 -2.175,-0.712 -2.4,-0.712 -2.419,-0.716 -2.435,-0.727 -2.446,-0.743 -2.45,-0.762 -2.45,-0.762 -2.45,-0.912 -2.443,-0.937 -2.425,-0.955 -2.4,-0.962 -2.4,-0.962 -2.175,-0.962 -2.156,-0.966 -2.14,-0.977 -2.129,-0.993 -2.125,-1.012 -2.125,-1.012 -2.125,-1.162 -2.129,-1.181 -2.14,-1.197 -2.156,-1.208 -2.175,-1.212 -2.175,-1.212 -2.4,-1.212 -2.419,-1.216 -2.435,-1.227 -2.446,-1.243 -2.45,-1.262 -2.45,-1.262 -2.45,-1.412 -2.443,-1.437 -2.425,-1.455 -2.4,-1.462 -2.4,-1.462 -2.175,-1.462 -2.156,-1.466 -2.14,-1.477 -2.129,-1.493 -2.125,-1.512 -2.125,-1.512 -2.125,-1.662 -2.129,-1.681 -2.14,-1.697 -2.156,-1.708 -2.175,-1.712 -2.175,-1.712 -2.4,-1.712 -2.419,-1.716 -2.435,-1.727 -2.446,-1.743 -2.45,-1.762 -2.45,-1.762 -2.45,-1.912 -2.443,-1.937 -2.425,-1.955 -2.4,-1.962 -2.4,-1.962 -2.175,-1.962 -2.156,-1.966 -2.14,-1.977 -2.129,-1.993 -2.125,-2.012 -2.125,-2.012 -2.125,-2.162 -2.129,-2.181 -2.14,-2.197 -2.156,-2.208 -2.175,-2.212 -2.175,-2.212 -2.4,-2.212 -2.419,-2.216 -2.435,-2.227 -2.446,-2.243 -2.45,-2.262 -2.45,-2.262 -2.45,-2.412 -2.443,-2.437 -2.425,-2.455 -2.4,-2.462 -2.4,-2.462 -2.175,-2.462 -2.156,-2.466 -2.14,-2.477 -2.129,-2.493 -2.125,-2.512 -2.125,-2.512 -2.125,-2.662 -2.129,-2.681 -2.14,-2.697 -2.156,-2.708 -2.175,-2.712 -2.175,-2.712 -2.4,-2.712 -2.419,-2.716 -2.435,-2.727 -2.446,-2.743 -2.45,-2.762 -2.45,-2.762 -2.45,-2.912 -2.443,-2.937 -2.425,-2.955 -2.4,-2.962 -2.4,-2.962 -2.175,-2.962 -2.156,-2.966 -2.14,-2.977 -2.129,-2.993 -2.125,-3.012 -2.125,-3.012 -2.125,-3.166 -2.118,-3.191 -2.1,-3.209 -2.075,-3.216 -2.075,-3.216 -1.8,-3.216 -1.781,-3.212 -1.765,-3.201 -1.754,-3.185 -1.75,-3.166 -1.75,-3.166 -1.75,0.492 -1.754,0.511 -1.765,0.527 -1.781,0.538 -1.8,0.542 -1.8,0.542
  silkscreen extent -3.12,-3.88 2.63,3.88, body extent -2.55,-3.8 2.55,3.8, height 0.25
VCHA105D [mm] "SMD, 2-Leads, Body 10.85x10mm"
  rrect2% 4.1x4.95 smd: 1(-4.75,0) 2(4.75,0)
  body extent -5.6,-5.15 5.6,5.15, height 5.4
WE-CMB_NiZn_S [mil] "TH, 4-Leads, Body 18.5x14.5mm"
  rect 95x95 hole 70: 1(-98.43,151.57)
  round 95 hole 70: 2(98.43,151.57) 3(98.43,-151.57) 4(-98.43,-151.57)
  silkscreen extent -256,-319 256,330, body extent -257,-319 257,319, height 770
WEEE_Minimum [mil] "WEEElie bin"
  silkscreen extent -95,-172 99,104

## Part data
AGND_CTRL1: library part CMP-0055148-2, "Test Point, Multipurpose, Black, TH", Color=Black, Manufacturer="Keystone Electronics", PartNumber=5011, Supplier Part Number 1=36-5011-ND
BODE: library part CMP-0055149-2, "Test Point, Multipurpose, White, TH", Color=White, Manufacturer="Keystone Electronics", PartNumber=5012, Supplier Part Number 1=36-5012-ND
C1: library part CMP-0011216-2, "CAP, AL, 100 uF, 80 V, +/- 20%, 0.32 ohm, AEC-Q200 Grade 2, SMD", Cap_Case=H13, Manufacturer=Panasonic, Supplier Part Number 1=PCE3493CT-ND, Tolerance_%=20%, Value1="0.32 ohm", Value2=80V, ValueDisplayed=100uF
